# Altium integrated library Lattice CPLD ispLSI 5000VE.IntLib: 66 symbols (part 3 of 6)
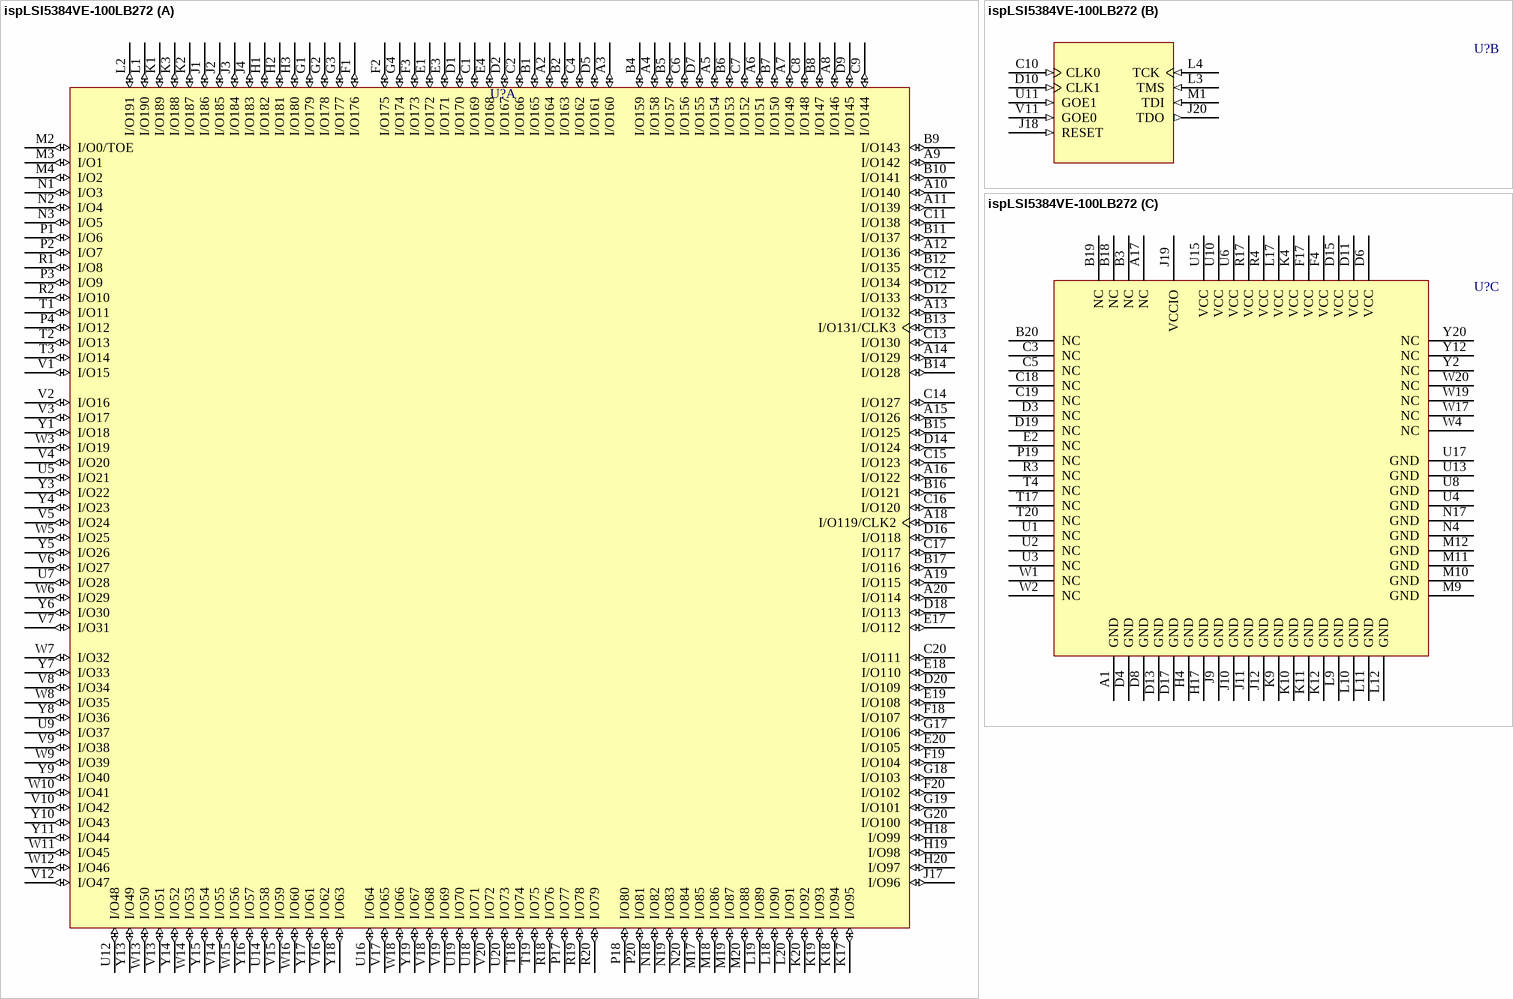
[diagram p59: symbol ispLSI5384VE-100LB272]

## ispLSI5384VE-100LB272
designator U?
ispLSI 5384VE SuperWIDE High Density PLD with 144 User I/Os, 10 ns, 3.3 V, Commercial Grade
footprint BGA272 (BGA, 272-Leads, Body 27x27mm, Pitch 1.27mm)
3D model 5384VE-BGA272 (272-Ball Ball Grid Array (BGA272))
part A pins: A2 I/O164 (io), A3 I/O160 (io), A4 I/O158 (io), A5 I/O154 (io), A6 I/O151 (io), A7 I/O149 (io), A8 I/O146 (io), A9 I/O142 (io), A10 I/O140 (io), A11 I/O139 (io), A12 I/O136 (io), A13 I/O132 (io), A14 I/O129 (io), A15 I/O126 (io), A16 I/O122 (io), A18 I/O119/CLK2 (io), A19 I/O115 (io), A20 I/O114 (io), B1 I/O165 (io), B2 I/O163 (io), B4 I/O159 (io), B5 I/O157 (io), B6 I/O153 (io), B7 I/O150 (io), B8 I/O147 (io), B9 I/O143 (io), B10 I/O141 (io), B11 I/O137 (io), B12 I/O135 (io), B13 I/O131/CLK3 (io), B14 I/O128 (io), B15 I/O125 (io), B16 I/O121 (io), B17 I/O116 (io), C1 I/O169 (io), C2 I/O166 (io), C4 I/O162 (io), C6 I/O156 (io), C7 I/O152 (io), C8 I/O148 (io), C9 I/O144 (io), C11 I/O138 (io), C12 I/O134 (io), C13 I/O130 (io), C14 I/O127 (io), C15 I/O123 (io), C16 I/O120 (io), C17 I/O117 (io), C20 I/O111 (io), D1 I/O170 (io), D2 I/O167 (io), D5 I/O161 (io), D7 I/O155 (io), D9 I/O145 (io), D12 I/O133 (io), D14 I/O124 (io), D16 I/O118 (io), D18 I/O113 (io), D20 I/O109 (io), E1 I/O172 (io), E3 I/O171 (io), E4 I/O168 (io), E17 I/O112 (io), E18 I/O110 (io), E19 I/O108 (io), E20 I/O105 (io), F1 I/O176 (io), F2 I/O175 (io), F3 I/O173 (io), F18 I/O107 (io), F19 I/O104 (io), F20 I/O102 (io), G1 I/O179 (io), G2 I/O178 (io), G3 I/O177 (io), G4 I/O174 (io), G17 I/O106 (io), G18 I/O103 (io), G19 I/O101 (io), G20 I/O100 (io), H1 I/O182 (io), H2 I/O181 (io), H3 I/O180 (io), H18 I/O99 (io), H19 I/O98 (io), H20 I/O97 (io), J1 I/O186 (io), J2 I/O185 (io), J3 I/O184 (io), J4 I/O183 (io), J17 I/O96 (io), K1 I/O189 (io), K2 I/O187 (io), K3 I/O188 (io), K17 I/O95 (io), K18 I/O94 (io), K19 I/O93 (io), K20 I/O92 (io), L1 I/O190 (io), L2 I/O191 (io), L18 I/O90 (io), L19 I/O89 (io), L20 I/O91 (io), M2 I/O0/TOE (io), M3 I/O1 (io), M4 I/O2 (io), M17 I/O85 (io), M18 I/O86 (io), M19 I/O87 (io), M20 I/O88 (io), N1 I/O3 (io), N2 I/O4 (io), N3 I/O5 (io), N18 I/O82 (io), N19 I/O83 (io), N20 I/O84 (io), P1 I/O6 (io), P2 I/O7 (io), P3 I/O9 (io), P4 I/O12 (io), P17 I/O77 (io), P18 I/O80 (io), P20 I/O81 (io), R1 I/O8 (io), R2 I/O10 (io), R18 I/O76 (io), R19 I/O78 (io), R20 I/O79 (io), T1 I/O11 (io), T2 I/O13 (io), T3 I/O14 (io), T18 I/O74 (io), T19 I/O75 (io), U5 I/O21 (io), U7 I/O28 (io), U9 I/O37 (io), U12 I/O48 (io), U14 I/O58 (io), U16 I/O64 (io), U18 I/O71 (io), U19 I/O70 (io), U20 I/O73 (io), V1 I/O15 (io), V2 I/O16 (io), V3 I/O17 (io), V4 I/O20 (io), V5 I/O24 (io), V6 I/O27 (io), V7 I/O31 (io), V8 I/O34 (io), V9 I/O38 (io), V10 I/O42 (io), V12 I/O47 (io), V13 I/O51 (io), V14 I/O55 (io), V15 I/O59 (io), V16 I/O62 (io), V17 I/O65 (io), V18 I/O68 (io), V19 I/O69 (io), V20 I/O72 (io), W3 I/O19 (io), W5 I/O25 (io), W6 I/O29 (io), W7 I/O32 (io), W8 I/O35 (io), W9 I/O39 (io), W10 I/O41 (io), W11 I/O45 (io), W12 I/O46 (io), W13 I/O50 (io), W14 I/O53 (io), W15 I/O56 (io), W16 I/O60 (io), W18 I/O66 (io), Y1 I/O18 (io), Y3 I/O22 (io), Y4 I/O23 (io), Y5 I/O26 (io), Y6 I/O30 (io), Y7 I/O33 (io), Y8 I/O36 (io), Y9 I/O40 (io), Y10 I/O43 (io), Y11 I/O44 (io), Y13 I/O49 (io), Y14 I/O52 (io), Y15 I/O54 (io), Y16 I/O57 (io), Y17 I/O61 (io), Y18 I/O63 (io), Y19 I/O67 (io)
part B pins: C10 CLK0 (in), D10 CLK1 (in), J18 RESET (in), J20 TDO (out), L3 TMS (in), L4 TCK (in), M1 TDI (in), U11 GOE1 (in), V11 GOE0 (in)
part C pins: A1 GND (power), A17 NC, B3 NC, B18 NC, B19 NC, B20 NC, C3 NC, C5 NC, C18 NC, C19 NC, D3 NC, D4 GND (power), D6 VCC (power), D8 GND (power), D11 VCC (power), D13 GND (power), D15 VCC (power), D17 GND (power), D19 NC, E2 NC, F4 VCC (power), F17 VCC (power), H4 GND (power), H17 GND (power), J9 GND (power), J10 GND (power), J11 GND (power), J12 GND (power), J19 VCCIO (power), K4 VCC (power), K9 GND (power), K10 GND (power), K11 GND (power), K12 GND (power), L9 GND (power), L10 GND (power), L11 GND (power), L12 GND (power), L17 VCC (power), M9 GND (power), M10 GND (power), M11 GND (power), M12 GND (power), N4 GND (power), N17 GND (power), P19 NC, R3 NC, R4 VCC (power), R17 VCC (power), T4 NC, T17 NC, T20 NC, U1 NC, U2 NC, U3 NC, U4 GND (power), U6 VCC (power), U8 GND (power), U10 VCC (power), U13 GND (power), U15 VCC (power), U17 GND (power), W1 NC, W2 NC, W4 NC, W17 NC, W19 NC, W20 NC, Y2 NC, Y12 NC, Y20 NC

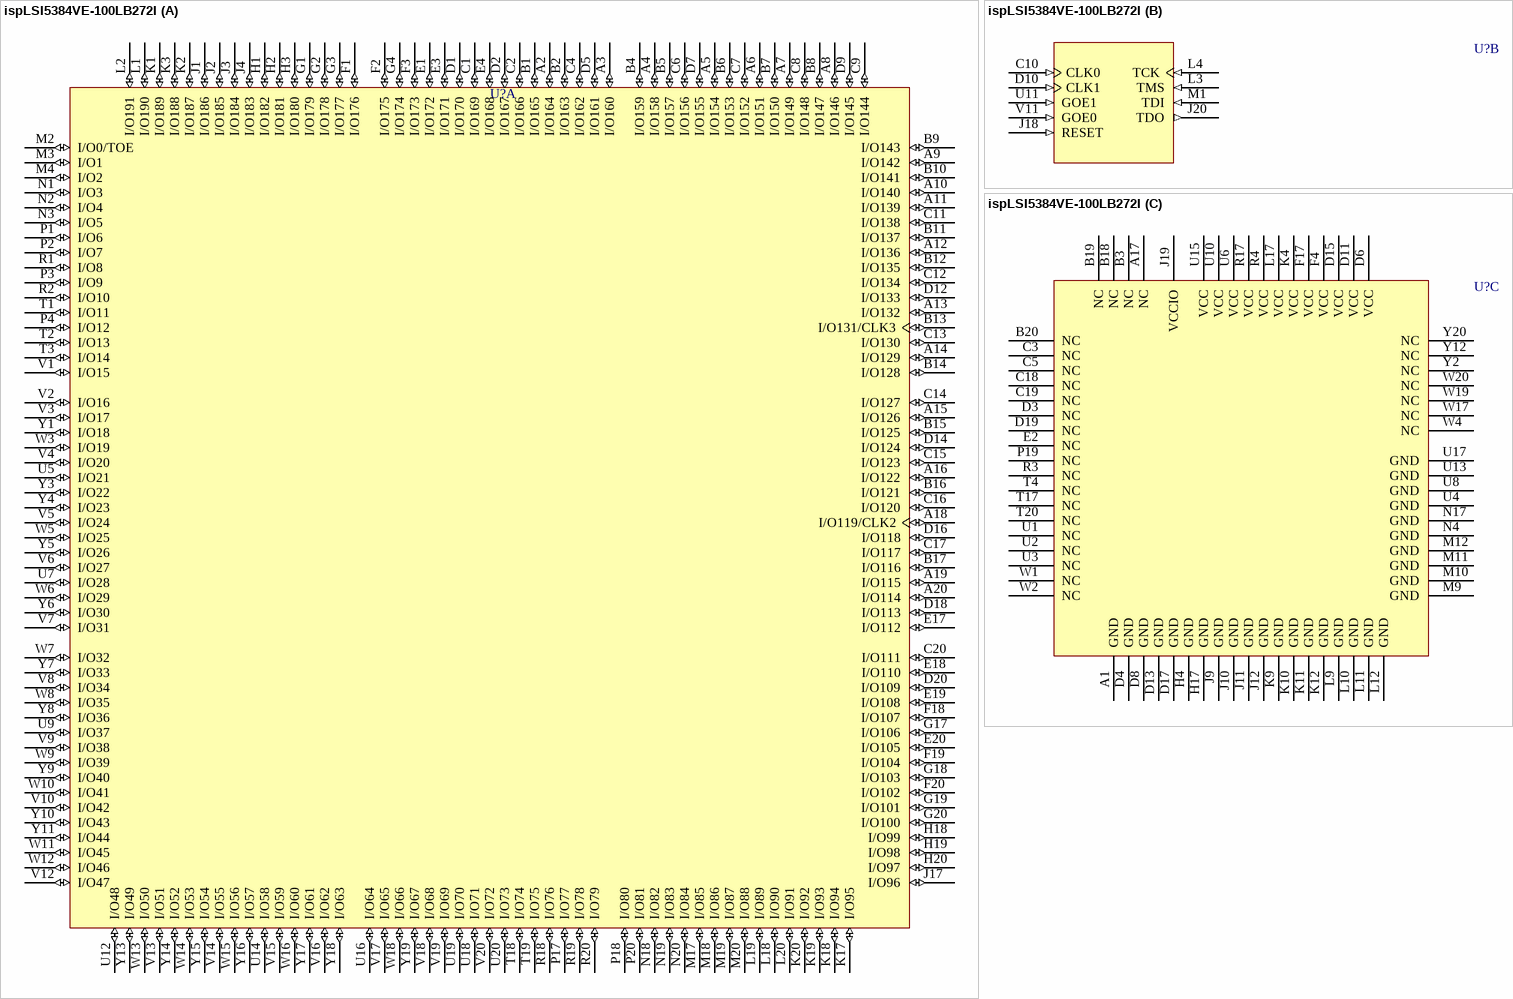
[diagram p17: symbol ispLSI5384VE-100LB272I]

## ispLSI5384VE-100LB272I
designator U?
ispLSI 5384VE SuperWIDE High Density PLD with 144 User I/Os, 10 ns, 3.3 V, Industrial Grade
footprint BGA272 (BGA, 272-Leads, Body 27x27mm, Pitch 1.27mm)
3D model 5384VE-BGA272 (272-Ball Ball Grid Array (BGA272))
part A pins: A2 I/O164 (io), A3 I/O160 (io), A4 I/O158 (io), A5 I/O154 (io), A6 I/O151 (io), A7 I/O149 (io), A8 I/O146 (io), A9 I/O142 (io), A10 I/O140 (io), A11 I/O139 (io), A12 I/O136 (io), A13 I/O132 (io), A14 I/O129 (io), A15 I/O126 (io), A16 I/O122 (io), A18 I/O119/CLK2 (io), A19 I/O115 (io), A20 I/O114 (io), B1 I/O165 (io), B2 I/O163 (io), B4 I/O159 (io), B5 I/O157 (io), B6 I/O153 (io), B7 I/O150 (io), B8 I/O147 (io), B9 I/O143 (io), B10 I/O141 (io), B11 I/O137 (io), B12 I/O135 (io), B13 I/O131/CLK3 (io), B14 I/O128 (io), B15 I/O125 (io), B16 I/O121 (io), B17 I/O116 (io), C1 I/O169 (io), C2 I/O166 (io), C4 I/O162 (io), C6 I/O156 (io), C7 I/O152 (io), C8 I/O148 (io), C9 I/O144 (io), C11 I/O138 (io), C12 I/O134 (io), C13 I/O130 (io), C14 I/O127 (io), C15 I/O123 (io), C16 I/O120 (io), C17 I/O117 (io), C20 I/O111 (io), D1 I/O170 (io), D2 I/O167 (io), D5 I/O161 (io), D7 I/O155 (io), D9 I/O145 (io), D12 I/O133 (io), D14 I/O124 (io), D16 I/O118 (io), D18 I/O113 (io), D20 I/O109 (io), E1 I/O172 (io), E3 I/O171 (io), E4 I/O168 (io), E17 I/O112 (io), E18 I/O110 (io), E19 I/O108 (io), E20 I/O105 (io), F1 I/O176 (io), F2 I/O175 (io), F3 I/O173 (io), F18 I/O107 (io), F19 I/O104 (io), F20 I/O102 (io), G1 I/O179 (io), G2 I/O178 (io), G3 I/O177 (io), G4 I/O174 (io), G17 I/O106 (io), G18 I/O103 (io), G19 I/O101 (io), G20 I/O100 (io), H1 I/O182 (io), H2 I/O181 (io), H3 I/O180 (io), H18 I/O99 (io), H19 I/O98 (io), H20 I/O97 (io), J1 I/O186 (io), J2 I/O185 (io), J3 I/O184 (io), J4 I/O183 (io), J17 I/O96 (io), K1 I/O189 (io), K2 I/O187 (io), K3 I/O188 (io), K17 I/O95 (io), K18 I/O94 (io), K19 I/O93 (io), K20 I/O92 (io), L1 I/O190 (io), L2 I/O191 (io), L18 I/O90 (io), L19 I/O89 (io), L20 I/O91 (io), M2 I/O0/TOE (io), M3 I/O1 (io), M4 I/O2 (io), M17 I/O85 (io), M18 I/O86 (io), M19 I/O87 (io), M20 I/O88 (io), N1 I/O3 (io), N2 I/O4 (io), N3 I/O5 (io), N18 I/O82 (io), N19 I/O83 (io), N20 I/O84 (io), P1 I/O6 (io), P2 I/O7 (io), P3 I/O9 (io), P4 I/O12 (io), P17 I/O77 (io), P18 I/O80 (io), P20 I/O81 (io), R1 I/O8 (io), R2 I/O10 (io), R18 I/O76 (io), R19 I/O78 (io), R20 I/O79 (io), T1 I/O11 (io), T2 I/O13 (io), T3 I/O14 (io), T18 I/O74 (io), T19 I/O75 (io), U5 I/O21 (io), U7 I/O28 (io), U9 I/O37 (io), U12 I/O48 (io), U14 I/O58 (io), U16 I/O64 (io), U18 I/O71 (io), U19 I/O70 (io), U20 I/O73 (io), V1 I/O15 (io), V2 I/O16 (io), V3 I/O17 (io), V4 I/O20 (io), V5 I/O24 (io), V6 I/O27 (io), V7 I/O31 (io), V8 I/O34 (io), V9 I/O38 (io), V10 I/O42 (io), V12 I/O47 (io), V13 I/O51 (io), V14 I/O55 (io), V15 I/O59 (io), V16 I/O62 (io), V17 I/O65 (io), V18 I/O68 (io), V19 I/O69 (io), V20 I/O72 (io), W3 I/O19 (io), W5 I/O25 (io), W6 I/O29 (io), W7 I/O32 (io), W8 I/O35 (io), W9 I/O39 (io), W10 I/O41 (io), W11 I/O45 (io), W12 I/O46 (io), W13 I/O50 (io), W14 I/O53 (io), W15 I/O56 (io), W16 I/O60 (io), W18 I/O66 (io), Y1 I/O18 (io), Y3 I/O22 (io), Y4 I/O23 (io), Y5 I/O26 (io), Y6 I/O30 (io), Y7 I/O33 (io), Y8 I/O36 (io), Y9 I/O40 (io), Y10 I/O43 (io), Y11 I/O44 (io), Y13 I/O49 (io), Y14 I/O52 (io), Y15 I/O54 (io), Y16 I/O57 (io), Y17 I/O61 (io), Y18 I/O63 (io), Y19 I/O67 (io)
part B pins: C10 CLK0 (in), D10 CLK1 (in), J18 RESET (in), J20 TDO (out), L3 TMS (in), L4 TCK (in), M1 TDI (in), U11 GOE1 (in), V11 GOE0 (in)
part C pins: A1 GND (power), A17 NC, B3 NC, B18 NC, B19 NC, B20 NC, C3 NC, C5 NC, C18 NC, C19 NC, D3 NC, D4 GND (power), D6 VCC (power), D8 GND (power), D11 VCC (power), D13 GND (power), D15 VCC (power), D17 GND (power), D19 NC, E2 NC, F4 VCC (power), F17 VCC (power), H4 GND (power), H17 GND (power), J9 GND (power), J10 GND (power), J11 GND (power), J12 GND (power), J19 VCCIO (power), K4 VCC (power), K9 GND (power), K10 GND (power), K11 GND (power), K12 GND (power), L9 GND (power), L10 GND (power), L11 GND (power), L12 GND (power), L17 VCC (power), M9 GND (power), M10 GND (power), M11 GND (power), M12 GND (power), N4 GND (power), N17 GND (power), P19 NC, R3 NC, R4 VCC (power), R17 VCC (power), T4 NC, T17 NC, T20 NC, U1 NC, U2 NC, U3 NC, U4 GND (power), U6 VCC (power), U8 GND (power), U10 VCC (power), U13 GND (power), U15 VCC (power), U17 GND (power), W1 NC, W2 NC, W4 NC, W17 NC, W19 NC, W20 NC, Y2 NC, Y12 NC, Y20 NC

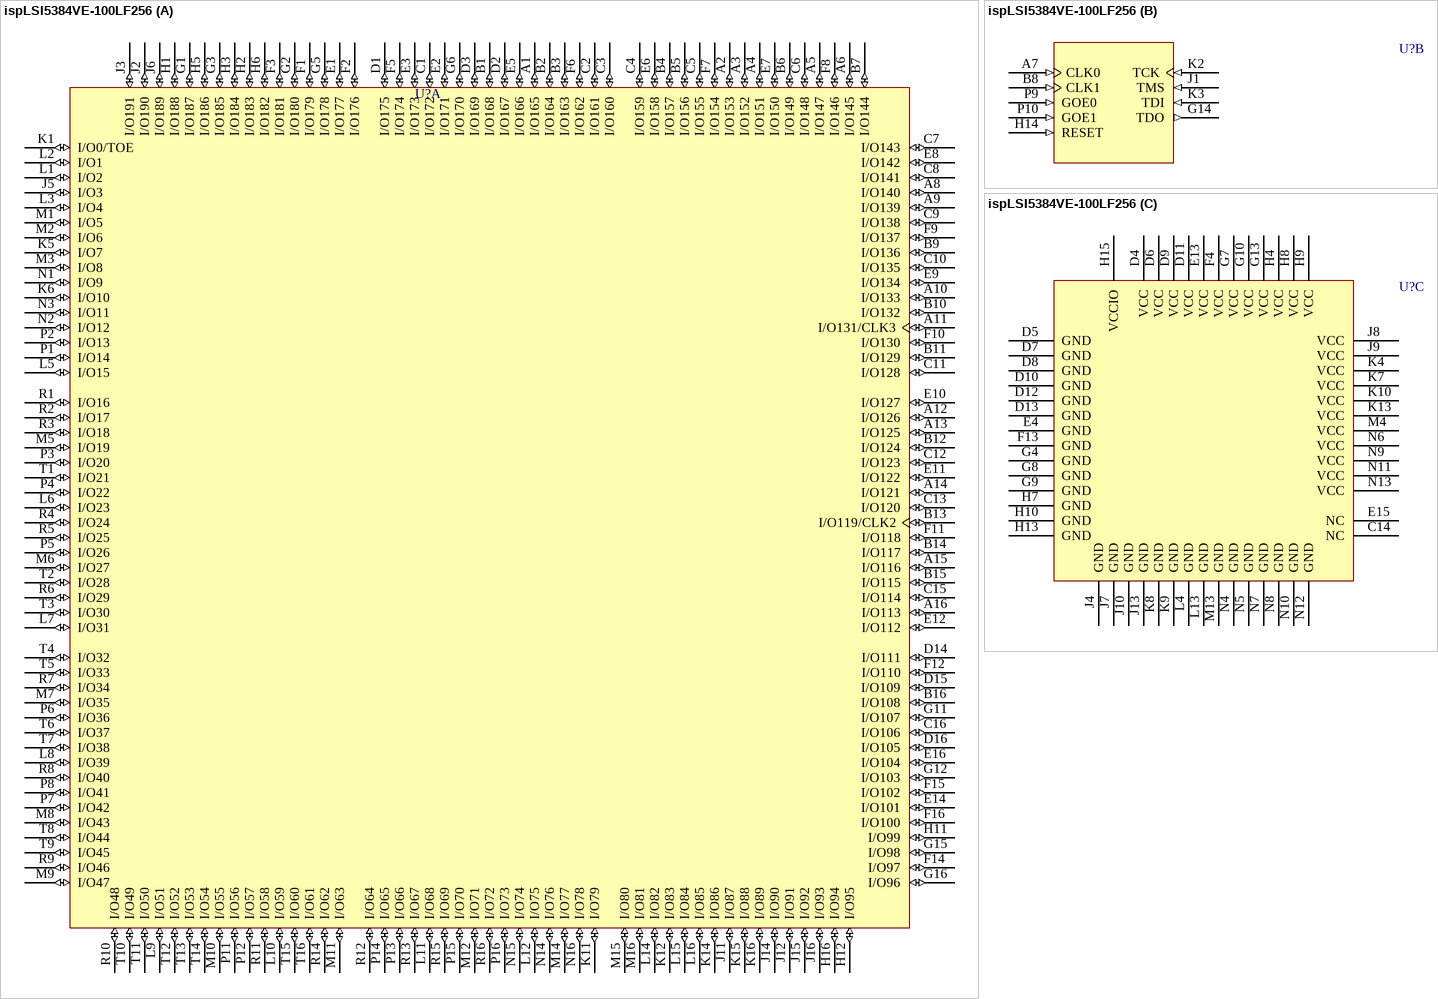
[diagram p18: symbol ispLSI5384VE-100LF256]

## ispLSI5384VE-100LF256
designator U?
ispLSI 5384VE SuperWIDE High Density PLD with 192 User I/Os, 10 ns, 3.3 V, Commercial Grade
footprint fpBGA256 (BGA, 256-Leads, Body 17x17mm, Pitch 1mm)
3D model 5384VE-fpBGA256 (256-Ball Fine Pitch Ball Grid Array (fpBGA256))
part A pins: A1 I/O165 (io), A2 I/O153 (io), A3 I/O152 (io), A4 I/O151 (io), A5 I/O147 (io), A6 I/O145 (io), A8 I/O140 (io), A9 I/O139 (io), A10 I/O133 (io), A11 I/O131/CLK3 (io), A12 I/O126 (io), A13 I/O125 (io), A14 I/O121 (io), A15 I/O116 (io), A16 I/O113 (io), B1 I/O168 (io), B2 I/O164 (io), B3 I/O163 (io), B4 I/O157 (io), B5 I/O156 (io), B6 I/O149 (io), B7 I/O144 (io), B9 I/O136 (io), B10 I/O132 (io), B11 I/O129 (io), B12 I/O124 (io), B13 I/O119/CLK2 (io), B14 I/O117 (io), B15 I/O115 (io), B16 I/O108 (io), C1 I/O172 (io), C2 I/O161 (io), C3 I/O160 (io), C4 I/O159 (io), C5 I/O155 (io), C6 I/O148 (io), C7 I/O143 (io), C8 I/O141 (io), C9 I/O138 (io), C10 I/O135 (io), C11 I/O128 (io), C12 I/O123 (io), C13 I/O120 (io), C15 I/O114 (io), C16 I/O106 (io), D1 I/O175 (io), D2 I/O167 (io), D3 I/O169 (io), D14 I/O111 (io), D15 I/O109 (io), D16 I/O105 (io), E1 I/O177 (io), E2 I/O171 (io), E3 I/O173 (io), E5 I/O166 (io), E6 I/O158 (io), E7 I/O150 (io), E8 I/O142 (io), E9 I/O134 (io), E10 I/O127 (io), E11 I/O122 (io), E12 I/O112 (io), E14 I/O101 (io), E16 I/O104 (io), F1 I/O179 (io), F2 I/O176 (io), F3 I/O181 (io), F5 I/O174 (io), F6 I/O162 (io), F7 I/O154 (io), F8 I/O146 (io), F9 I/O137 (io), F10 I/O130 (io), F11 I/O118 (io), F12 I/O110 (io), F14 I/O97 (io), F15 I/O102 (io), F16 I/O100 (io), G1 I/O187 (io), G2 I/O180 (io), G3 I/O185 (io), G5 I/O178 (io), G6 I/O170 (io), G11 I/O107 (io), G12 I/O103 (io), G15 I/O98 (io), G16 I/O96 (io), H1 I/O188 (io), H2 I/O183 (io), H3 I/O184 (io), H5 I/O186 (io), H6 I/O182 (io), H11 I/O99 (io), H12 I/O95 (io), H16 I/O94 (io), J2 I/O190 (io), J3 I/O191 (io), J5 I/O3 (io), J6 I/O189 (io), J11 I/O87 (io), J12 I/O91 (io), J14 I/O90 (io), J15 I/O92 (io), J16 I/O93 (io), K1 I/O0/TOE (io), K5 I/O7 (io), K6 I/O10 (io), K11 I/O79 (io), K12 I/O83 (io), K14 I/O86 (io), K15 I/O88 (io), K16 I/O89 (io), L1 I/O2 (io), L2 I/O1 (io), L3 I/O4 (io), L5 I/O15 (io), L6 I/O23 (io), L7 I/O31 (io), L8 I/O39 (io), L9 I/O51 (io), L10 I/O59 (io), L11 I/O68 (io), L12 I/O75 (io), L14 I/O82 (io), L15 I/O84 (io), L16 I/O85 (io), M1 I/O5 (io), M2 I/O6 (io), M3 I/O8 (io), M5 I/O19 (io), M6 I/O27 (io), M7 I/O35 (io), M8 I/O43 (io), M9 I/O47 (io), M10 I/O55 (io), M11 I/O63 (io), M12 I/O71 (io), M14 I/O77 (io), M15 I/O80 (io), M16 I/O81 (io), N1 I/O9 (io), N2 I/O12 (io), N3 I/O11 (io), N14 I/O76 (io), N15 I/O74 (io), N16 I/O78 (io), P1 I/O14 (io), P2 I/O13 (io), P3 I/O20 (io), P4 I/O22 (io), P5 I/O26 (io), P6 I/O36 (io), P7 I/O42 (io), P8 I/O41 (io), P11 I/O56 (io), P12 I/O57 (io), P13 I/O66 (io), P14 I/O65 (io), P15 I/O70 (io), P16 I/O73 (io), R1 I/O16 (io), R2 I/O17 (io), R3 I/O18 (io), R4 I/O24 (io), R5 I/O25 (io), R6 I/O29 (io), R7 I/O34 (io), R8 I/O40 (io), R9 I/O46 (io), R10 I/O48 (io), R11 I/O58 (io), R12 I/O64 (io), R13 I/O67 (io), R14 I/O62 (io), R15 I/O69 (io), R16 I/O72 (io), T1 I/O21 (io), T2 I/O28 (io), T3 I/O30 (io), T4 I/O32 (io), T5 I/O33 (io), T6 I/O37 (io), T7 I/O38 (io), T8 I/O44 (io), T9 I/O45 (io), T10 I/O49 (io), T11 I/O50 (io), T12 I/O52 (io), T13 I/O53 (io), T14 I/O54 (io), T15 I/O60 (io), T16 I/O61 (io)
part B pins: A7 CLK0 (in), B8 CLK1 (in), G14 TDO (out), H14 RESET (in), J1 TMS (in), K2 TCK (in), K3 TDI (in), P9 GOE0 (in), P10 GOE1 (in)
part C pins: C14 NC, D4 VCC (power), D5 GND (power), D6 VCC (power), D7 GND (power), D8 GND (power), D9 VCC (power), D10 GND (power), D11 VCC (power), D12 GND (power), D13 GND (power), E4 GND (power), E13 VCC (power), E15 NC, F4 VCC (power), F13 GND (power), G4 GND (power), G7 VCC (power), G8 GND (power), G9 GND (power), G10 VCC (power), G13 VCC (power), H4 VCC (power), H7 GND (power), H8 VCC (power), H9 VCC (power), H10 GND (power), H13 GND (power), H15 VCCIO (power), J4 GND (power), J7 GND (power), J8 VCC (power), J9 VCC (power), J10 GND (power), J13 GND (power), K4 VCC (power), K7 VCC (power), K8 GND (power), K9 GND (power), K10 VCC (power), K13 VCC (power), L4 GND (power), L13 GND (power), M4 VCC (power), M13 GND (power), N4 GND (power), N5 GND (power), N6 VCC (power), N7 GND (power), N8 GND (power), N9 VCC (power), N10 GND (power), N11 VCC (power), N12 GND (power), N13 VCC (power)

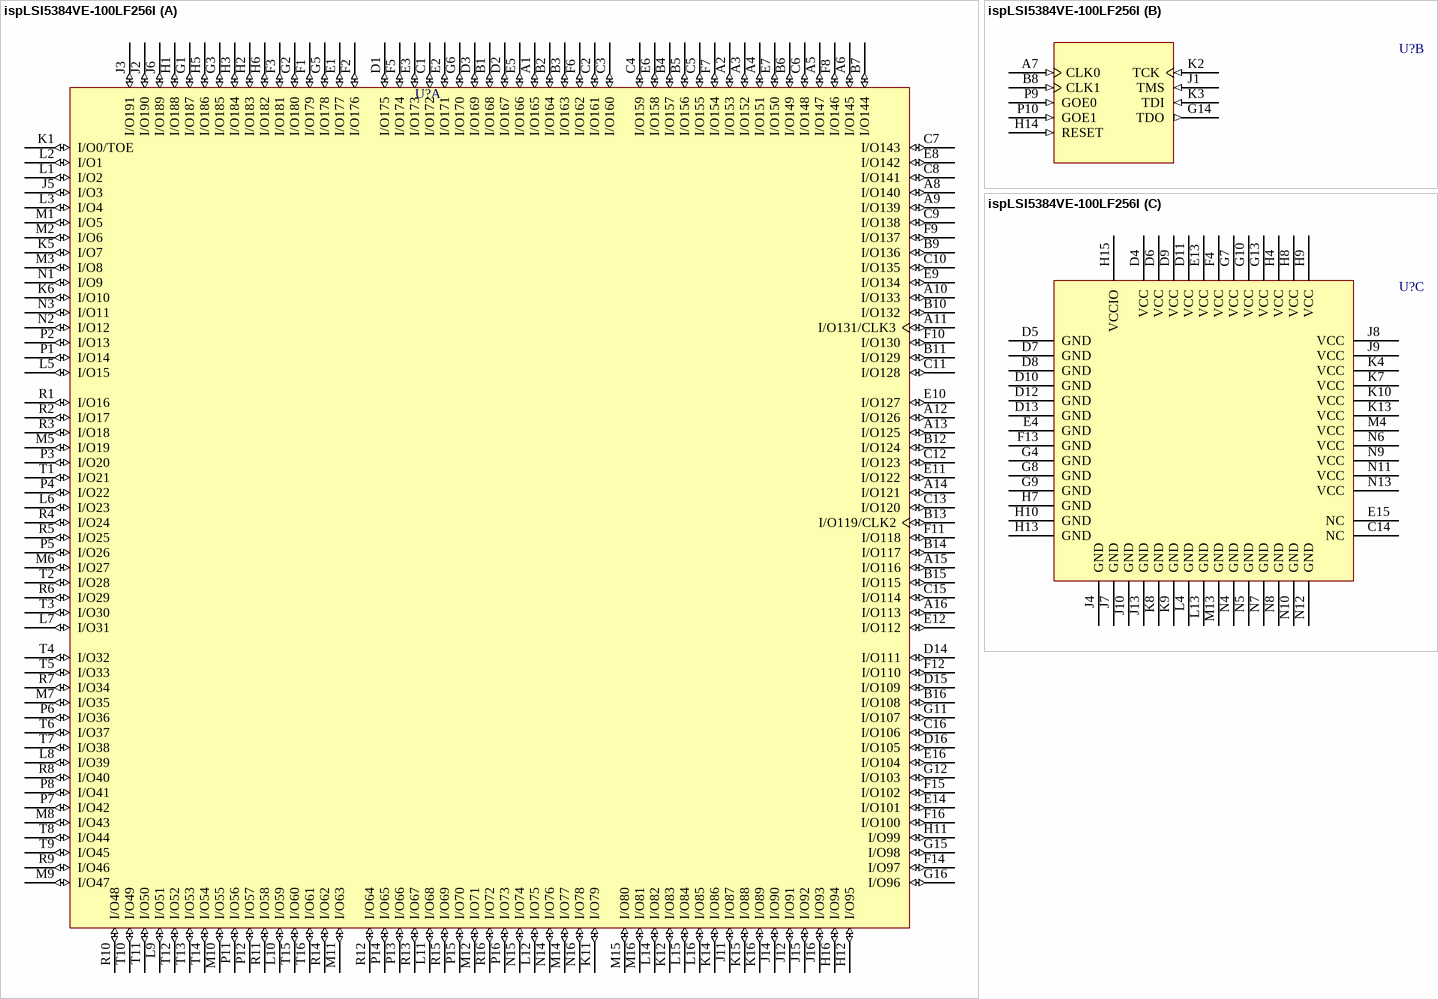
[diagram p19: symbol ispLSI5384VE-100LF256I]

## ispLSI5384VE-100LF256I
designator U?
ispLSI 5384VE SuperWIDE High Density PLD with 192 User I/Os, 10 ns, 3.3 V, Industrial Grade
footprint fpBGA256 (BGA, 256-Leads, Body 17x17mm, Pitch 1mm)
3D model 5384VE-fpBGA256 (256-Ball Fine Pitch Ball Grid Array (fpBGA256))
part A pins: A1 I/O165 (io), A2 I/O153 (io), A3 I/O152 (io), A4 I/O151 (io), A5 I/O147 (io), A6 I/O145 (io), A8 I/O140 (io), A9 I/O139 (io), A10 I/O133 (io), A11 I/O131/CLK3 (io), A12 I/O126 (io), A13 I/O125 (io), A14 I/O121 (io), A15 I/O116 (io), A16 I/O113 (io), B1 I/O168 (io), B2 I/O164 (io), B3 I/O163 (io), B4 I/O157 (io), B5 I/O156 (io), B6 I/O149 (io), B7 I/O144 (io), B9 I/O136 (io), B10 I/O132 (io), B11 I/O129 (io), B12 I/O124 (io), B13 I/O119/CLK2 (io), B14 I/O117 (io), B15 I/O115 (io), B16 I/O108 (io), C1 I/O172 (io), C2 I/O161 (io), C3 I/O160 (io), C4 I/O159 (io), C5 I/O155 (io), C6 I/O148 (io), C7 I/O143 (io), C8 I/O141 (io), C9 I/O138 (io), C10 I/O135 (io), C11 I/O128 (io), C12 I/O123 (io), C13 I/O120 (io), C15 I/O114 (io), C16 I/O106 (io), D1 I/O175 (io), D2 I/O167 (io), D3 I/O169 (io), D14 I/O111 (io), D15 I/O109 (io), D16 I/O105 (io), E1 I/O177 (io), E2 I/O171 (io), E3 I/O173 (io), E5 I/O166 (io), E6 I/O158 (io), E7 I/O150 (io), E8 I/O142 (io), E9 I/O134 (io), E10 I/O127 (io), E11 I/O122 (io), E12 I/O112 (io), E14 I/O101 (io), E16 I/O104 (io), F1 I/O179 (io), F2 I/O176 (io), F3 I/O181 (io), F5 I/O174 (io), F6 I/O162 (io), F7 I/O154 (io), F8 I/O146 (io), F9 I/O137 (io), F10 I/O130 (io), F11 I/O118 (io), F12 I/O110 (io), F14 I/O97 (io), F15 I/O102 (io), F16 I/O100 (io), G1 I/O187 (io), G2 I/O180 (io), G3 I/O185 (io), G5 I/O178 (io), G6 I/O170 (io), G11 I/O107 (io), G12 I/O103 (io), G15 I/O98 (io), G16 I/O96 (io), H1 I/O188 (io), H2 I/O183 (io), H3 I/O184 (io), H5 I/O186 (io), H6 I/O182 (io), H11 I/O99 (io), H12 I/O95 (io), H16 I/O94 (io), J2 I/O190 (io), J3 I/O191 (io), J5 I/O3 (io), J6 I/O189 (io), J11 I/O87 (io), J12 I/O91 (io), J14 I/O90 (io), J15 I/O92 (io), J16 I/O93 (io), K1 I/O0/TOE (io), K5 I/O7 (io), K6 I/O10 (io), K11 I/O79 (io), K12 I/O83 (io), K14 I/O86 (io), K15 I/O88 (io), K16 I/O89 (io), L1 I/O2 (io), L2 I/O1 (io), L3 I/O4 (io), L5 I/O15 (io), L6 I/O23 (io), L7 I/O31 (io), L8 I/O39 (io), L9 I/O51 (io), L10 I/O59 (io), L11 I/O68 (io), L12 I/O75 (io), L14 I/O82 (io), L15 I/O84 (io), L16 I/O85 (io), M1 I/O5 (io), M2 I/O6 (io), M3 I/O8 (io), M5 I/O19 (io), M6 I/O27 (io), M7 I/O35 (io), M8 I/O43 (io), M9 I/O47 (io), M10 I/O55 (io), M11 I/O63 (io), M12 I/O71 (io), M14 I/O77 (io), M15 I/O80 (io), M16 I/O81 (io), N1 I/O9 (io), N2 I/O12 (io), N3 I/O11 (io), N14 I/O76 (io), N15 I/O74 (io), N16 I/O78 (io), P1 I/O14 (io), P2 I/O13 (io), P3 I/O20 (io), P4 I/O22 (io), P5 I/O26 (io), P6 I/O36 (io), P7 I/O42 (io), P8 I/O41 (io), P11 I/O56 (io), P12 I/O57 (io), P13 I/O66 (io), P14 I/O65 (io), P15 I/O70 (io), P16 I/O73 (io), R1 I/O16 (io), R2 I/O17 (io), R3 I/O18 (io), R4 I/O24 (io), R5 I/O25 (io), R6 I/O29 (io), R7 I/O34 (io), R8 I/O40 (io), R9 I/O46 (io), R10 I/O48 (io), R11 I/O58 (io), R12 I/O64 (io), R13 I/O67 (io), R14 I/O62 (io), R15 I/O69 (io), R16 I/O72 (io), T1 I/O21 (io), T2 I/O28 (io), T3 I/O30 (io), T4 I/O32 (io), T5 I/O33 (io), T6 I/O37 (io), T7 I/O38 (io), T8 I/O44 (io), T9 I/O45 (io), T10 I/O49 (io), T11 I/O50 (io), T12 I/O52 (io), T13 I/O53 (io), T14 I/O54 (io), T15 I/O60 (io), T16 I/O61 (io)
part B pins: A7 CLK0 (in), B8 CLK1 (in), G14 TDO (out), H14 RESET (in), J1 TMS (in), K2 TCK (in), K3 TDI (in), P9 GOE0 (in), P10 GOE1 (in)
part C pins: C14 NC, D4 VCC (power), D5 GND (power), D6 VCC (power), D7 GND (power), D8 GND (power), D9 VCC (power), D10 GND (power), D11 VCC (power), D12 GND (power), D13 GND (power), E4 GND (power), E13 VCC (power), E15 NC, F4 VCC (power), F13 GND (power), G4 GND (power), G7 VCC (power), G8 GND (power), G9 GND (power), G10 VCC (power), G13 VCC (power), H4 VCC (power), H7 GND (power), H8 VCC (power), H9 VCC (power), H10 GND (power), H13 GND (power), H15 VCCIO (power), J4 GND (power), J7 GND (power), J8 VCC (power), J9 VCC (power), J10 GND (power), J13 GND (power), K4 VCC (power), K7 VCC (power), K8 GND (power), K9 GND (power), K10 VCC (power), K13 VCC (power), L4 GND (power), L13 GND (power), M4 VCC (power), M13 GND (power), N4 GND (power), N5 GND (power), N6 VCC (power), N7 GND (power), N8 GND (power), N9 VCC (power), N10 GND (power), N11 VCC (power), N12 GND (power), N13 VCC (power)

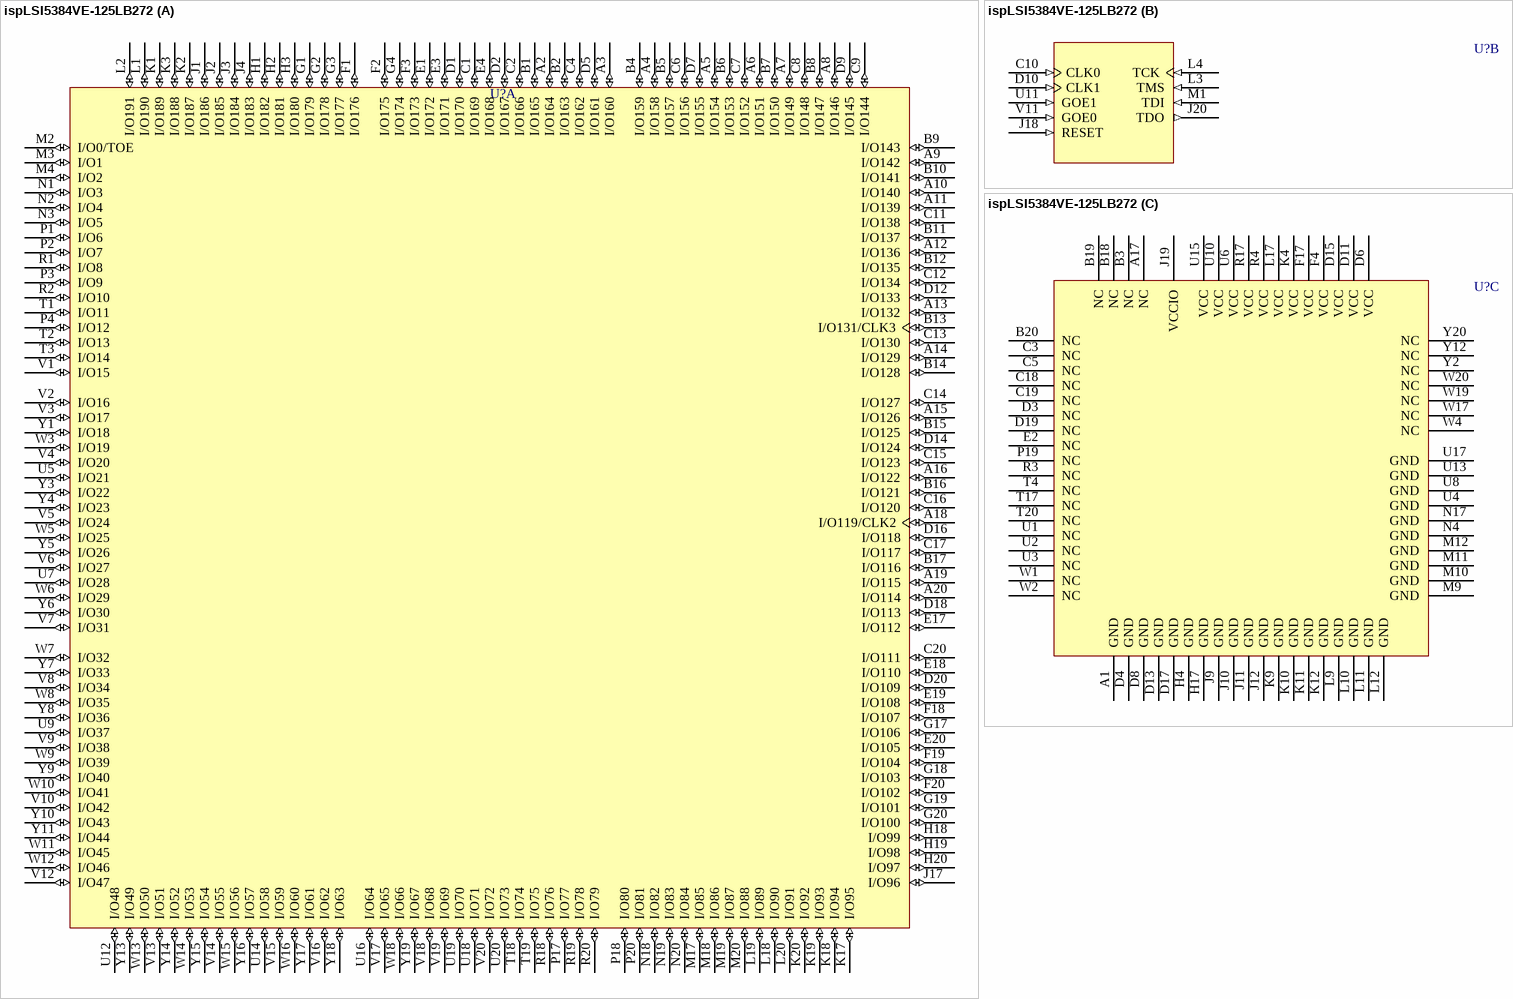
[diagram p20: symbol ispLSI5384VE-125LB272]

## ispLSI5384VE-125LB272
designator U?
ispLSI 5384VE SuperWIDE High Density PLD with 144 User I/Os, 7.5 ns, 3.3 V, Commercial Grade
footprint BGA272 (BGA, 272-Leads, Body 27x27mm, Pitch 1.27mm)
3D model 5384VE-BGA272 (272-Ball Ball Grid Array (BGA272))
part A pins: A2 I/O164 (io), A3 I/O160 (io), A4 I/O158 (io), A5 I/O154 (io), A6 I/O151 (io), A7 I/O149 (io), A8 I/O146 (io), A9 I/O142 (io), A10 I/O140 (io), A11 I/O139 (io), A12 I/O136 (io), A13 I/O132 (io), A14 I/O129 (io), A15 I/O126 (io), A16 I/O122 (io), A18 I/O119/CLK2 (io), A19 I/O115 (io), A20 I/O114 (io), B1 I/O165 (io), B2 I/O163 (io), B4 I/O159 (io), B5 I/O157 (io), B6 I/O153 (io), B7 I/O150 (io), B8 I/O147 (io), B9 I/O143 (io), B10 I/O141 (io), B11 I/O137 (io), B12 I/O135 (io), B13 I/O131/CLK3 (io), B14 I/O128 (io), B15 I/O125 (io), B16 I/O121 (io), B17 I/O116 (io), C1 I/O169 (io), C2 I/O166 (io), C4 I/O162 (io), C6 I/O156 (io), C7 I/O152 (io), C8 I/O148 (io), C9 I/O144 (io), C11 I/O138 (io), C12 I/O134 (io), C13 I/O130 (io), C14 I/O127 (io), C15 I/O123 (io), C16 I/O120 (io), C17 I/O117 (io), C20 I/O111 (io), D1 I/O170 (io), D2 I/O167 (io), D5 I/O161 (io), D7 I/O155 (io), D9 I/O145 (io), D12 I/O133 (io), D14 I/O124 (io), D16 I/O118 (io), D18 I/O113 (io), D20 I/O109 (io), E1 I/O172 (io), E3 I/O171 (io), E4 I/O168 (io), E17 I/O112 (io), E18 I/O110 (io), E19 I/O108 (io), E20 I/O105 (io), F1 I/O176 (io), F2 I/O175 (io), F3 I/O173 (io), F18 I/O107 (io), F19 I/O104 (io), F20 I/O102 (io), G1 I/O179 (io), G2 I/O178 (io), G3 I/O177 (io), G4 I/O174 (io), G17 I/O106 (io), G18 I/O103 (io), G19 I/O101 (io), G20 I/O100 (io), H1 I/O182 (io), H2 I/O181 (io), H3 I/O180 (io), H18 I/O99 (io), H19 I/O98 (io), H20 I/O97 (io), J1 I/O186 (io), J2 I/O185 (io), J3 I/O184 (io), J4 I/O183 (io), J17 I/O96 (io), K1 I/O189 (io), K2 I/O187 (io), K3 I/O188 (io), K17 I/O95 (io), K18 I/O94 (io), K19 I/O93 (io), K20 I/O92 (io), L1 I/O190 (io), L2 I/O191 (io), L18 I/O90 (io), L19 I/O89 (io), L20 I/O91 (io), M2 I/O0/TOE (io), M3 I/O1 (io), M4 I/O2 (io), M17 I/O85 (io), M18 I/O86 (io), M19 I/O87 (io), M20 I/O88 (io), N1 I/O3 (io), N2 I/O4 (io), N3 I/O5 (io), N18 I/O82 (io), N19 I/O83 (io), N20 I/O84 (io), P1 I/O6 (io), P2 I/O7 (io), P3 I/O9 (io), P4 I/O12 (io), P17 I/O77 (io), P18 I/O80 (io), P20 I/O81 (io), R1 I/O8 (io), R2 I/O10 (io), R18 I/O76 (io), R19 I/O78 (io), R20 I/O79 (io), T1 I/O11 (io), T2 I/O13 (io), T3 I/O14 (io), T18 I/O74 (io), T19 I/O75 (io), U5 I/O21 (io), U7 I/O28 (io), U9 I/O37 (io), U12 I/O48 (io), U14 I/O58 (io), U16 I/O64 (io), U18 I/O71 (io), U19 I/O70 (io), U20 I/O73 (io), V1 I/O15 (io), V2 I/O16 (io), V3 I/O17 (io), V4 I/O20 (io), V5 I/O24 (io), V6 I/O27 (io), V7 I/O31 (io), V8 I/O34 (io), V9 I/O38 (io), V10 I/O42 (io), V12 I/O47 (io), V13 I/O51 (io), V14 I/O55 (io), V15 I/O59 (io), V16 I/O62 (io), V17 I/O65 (io), V18 I/O68 (io), V19 I/O69 (io), V20 I/O72 (io), W3 I/O19 (io), W5 I/O25 (io), W6 I/O29 (io), W7 I/O32 (io), W8 I/O35 (io), W9 I/O39 (io), W10 I/O41 (io), W11 I/O45 (io), W12 I/O46 (io), W13 I/O50 (io), W14 I/O53 (io), W15 I/O56 (io), W16 I/O60 (io), W18 I/O66 (io), Y1 I/O18 (io), Y3 I/O22 (io), Y4 I/O23 (io), Y5 I/O26 (io), Y6 I/O30 (io), Y7 I/O33 (io), Y8 I/O36 (io), Y9 I/O40 (io), Y10 I/O43 (io), Y11 I/O44 (io), Y13 I/O49 (io), Y14 I/O52 (io), Y15 I/O54 (io), Y16 I/O57 (io), Y17 I/O61 (io), Y18 I/O63 (io), Y19 I/O67 (io)
part B pins: C10 CLK0 (in), D10 CLK1 (in), J18 RESET (in), J20 TDO (out), L3 TMS (in), L4 TCK (in), M1 TDI (in), U11 GOE1 (in), V11 GOE0 (in)
part C pins: A1 GND (power), A17 NC, B3 NC, B18 NC, B19 NC, B20 NC, C3 NC, C5 NC, C18 NC, C19 NC, D3 NC, D4 GND (power), D6 VCC (power), D8 GND (power), D11 VCC (power), D13 GND (power), D15 VCC (power), D17 GND (power), D19 NC, E2 NC, F4 VCC (power), F17 VCC (power), H4 GND (power), H17 GND (power), J9 GND (power), J10 GND (power), J11 GND (power), J12 GND (power), J19 VCCIO (power), K4 VCC (power), K9 GND (power), K10 GND (power), K11 GND (power), K12 GND (power), L9 GND (power), L10 GND (power), L11 GND (power), L12 GND (power), L17 VCC (power), M9 GND (power), M10 GND (power), M11 GND (power), M12 GND (power), N4 GND (power), N17 GND (power), P19 NC, R3 NC, R4 VCC (power), R17 VCC (power), T4 NC, T17 NC, T20 NC, U1 NC, U2 NC, U3 NC, U4 GND (power), U6 VCC (power), U8 GND (power), U10 VCC (power), U13 GND (power), U15 VCC (power), U17 GND (power), W1 NC, W2 NC, W4 NC, W17 NC, W19 NC, W20 NC, Y2 NC, Y12 NC, Y20 NC

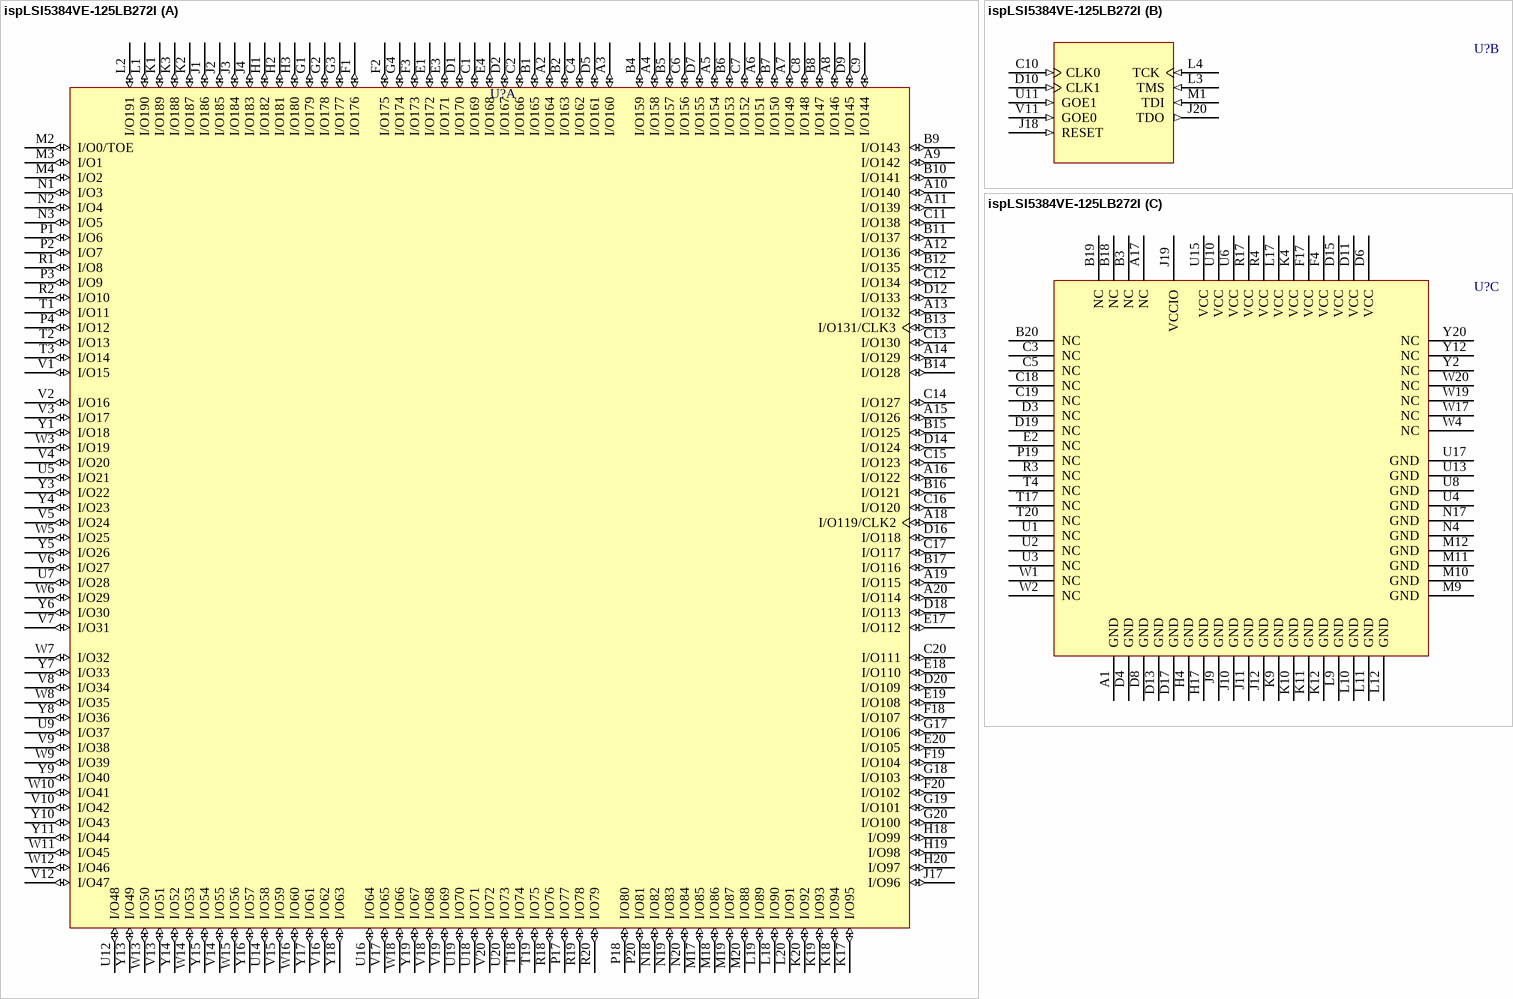
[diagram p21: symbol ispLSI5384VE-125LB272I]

## ispLSI5384VE-125LB272I
designator U?
ispLSI 5384VE SuperWIDE High Density PLD with 144 User I/Os, 7.5 ns, 3.3 V, Industrial Grade
footprint BGA272 (BGA, 272-Leads, Body 27x27mm, Pitch 1.27mm)
3D model 5384VE-BGA272 (272-Ball Ball Grid Array (BGA272))
part A pins: A2 I/O164 (io), A3 I/O160 (io), A4 I/O158 (io), A5 I/O154 (io), A6 I/O151 (io), A7 I/O149 (io), A8 I/O146 (io), A9 I/O142 (io), A10 I/O140 (io), A11 I/O139 (io), A12 I/O136 (io), A13 I/O132 (io), A14 I/O129 (io), A15 I/O126 (io), A16 I/O122 (io), A18 I/O119/CLK2 (io), A19 I/O115 (io), A20 I/O114 (io), B1 I/O165 (io), B2 I/O163 (io), B4 I/O159 (io), B5 I/O157 (io), B6 I/O153 (io), B7 I/O150 (io), B8 I/O147 (io), B9 I/O143 (io), B10 I/O141 (io), B11 I/O137 (io), B12 I/O135 (io), B13 I/O131/CLK3 (io), B14 I/O128 (io), B15 I/O125 (io), B16 I/O121 (io), B17 I/O116 (io), C1 I/O169 (io), C2 I/O166 (io), C4 I/O162 (io), C6 I/O156 (io), C7 I/O152 (io), C8 I/O148 (io), C9 I/O144 (io), C11 I/O138 (io), C12 I/O134 (io), C13 I/O130 (io), C14 I/O127 (io), C15 I/O123 (io), C16 I/O120 (io), C17 I/O117 (io), C20 I/O111 (io), D1 I/O170 (io), D2 I/O167 (io), D5 I/O161 (io), D7 I/O155 (io), D9 I/O145 (io), D12 I/O133 (io), D14 I/O124 (io), D16 I/O118 (io), D18 I/O113 (io), D20 I/O109 (io), E1 I/O172 (io), E3 I/O171 (io), E4 I/O168 (io), E17 I/O112 (io), E18 I/O110 (io), E19 I/O108 (io), E20 I/O105 (io), F1 I/O176 (io), F2 I/O175 (io), F3 I/O173 (io), F18 I/O107 (io), F19 I/O104 (io), F20 I/O102 (io), G1 I/O179 (io), G2 I/O178 (io), G3 I/O177 (io), G4 I/O174 (io), G17 I/O106 (io), G18 I/O103 (io), G19 I/O101 (io), G20 I/O100 (io), H1 I/O182 (io), H2 I/O181 (io), H3 I/O180 (io), H18 I/O99 (io), H19 I/O98 (io), H20 I/O97 (io), J1 I/O186 (io), J2 I/O185 (io), J3 I/O184 (io), J4 I/O183 (io), J17 I/O96 (io), K1 I/O189 (io), K2 I/O187 (io), K3 I/O188 (io), K17 I/O95 (io), K18 I/O94 (io), K19 I/O93 (io), K20 I/O92 (io), L1 I/O190 (io), L2 I/O191 (io), L18 I/O90 (io), L19 I/O89 (io), L20 I/O91 (io), M2 I/O0/TOE (io), M3 I/O1 (io), M4 I/O2 (io), M17 I/O85 (io), M18 I/O86 (io), M19 I/O87 (io), M20 I/O88 (io), N1 I/O3 (io), N2 I/O4 (io), N3 I/O5 (io), N18 I/O82 (io), N19 I/O83 (io), N20 I/O84 (io), P1 I/O6 (io), P2 I/O7 (io), P3 I/O9 (io), P4 I/O12 (io), P17 I/O77 (io), P18 I/O80 (io), P20 I/O81 (io), R1 I/O8 (io), R2 I/O10 (io), R18 I/O76 (io), R19 I/O78 (io), R20 I/O79 (io), T1 I/O11 (io), T2 I/O13 (io), T3 I/O14 (io), T18 I/O74 (io), T19 I/O75 (io), U5 I/O21 (io), U7 I/O28 (io), U9 I/O37 (io), U12 I/O48 (io), U14 I/O58 (io), U16 I/O64 (io), U18 I/O71 (io), U19 I/O70 (io), U20 I/O73 (io), V1 I/O15 (io), V2 I/O16 (io), V3 I/O17 (io), V4 I/O20 (io), V5 I/O24 (io), V6 I/O27 (io), V7 I/O31 (io), V8 I/O34 (io), V9 I/O38 (io), V10 I/O42 (io), V12 I/O47 (io), V13 I/O51 (io), V14 I/O55 (io), V15 I/O59 (io), V16 I/O62 (io), V17 I/O65 (io), V18 I/O68 (io), V19 I/O69 (io), V20 I/O72 (io), W3 I/O19 (io), W5 I/O25 (io), W6 I/O29 (io), W7 I/O32 (io), W8 I/O35 (io), W9 I/O39 (io), W10 I/O41 (io), W11 I/O45 (io), W12 I/O46 (io), W13 I/O50 (io), W14 I/O53 (io), W15 I/O56 (io), W16 I/O60 (io), W18 I/O66 (io), Y1 I/O18 (io), Y3 I/O22 (io), Y4 I/O23 (io), Y5 I/O26 (io), Y6 I/O30 (io), Y7 I/O33 (io), Y8 I/O36 (io), Y9 I/O40 (io), Y10 I/O43 (io), Y11 I/O44 (io), Y13 I/O49 (io), Y14 I/O52 (io), Y15 I/O54 (io), Y16 I/O57 (io), Y17 I/O61 (io), Y18 I/O63 (io), Y19 I/O67 (io)
part B pins: C10 CLK0 (in), D10 CLK1 (in), J18 RESET (in), J20 TDO (out), L3 TMS (in), L4 TCK (in), M1 TDI (in), U11 GOE1 (in), V11 GOE0 (in)
part C pins: A1 GND (power), A17 NC, B3 NC, B18 NC, B19 NC, B20 NC, C3 NC, C5 NC, C18 NC, C19 NC, D3 NC, D4 GND (power), D6 VCC (power), D8 GND (power), D11 VCC (power), D13 GND (power), D15 VCC (power), D17 GND (power), D19 NC, E2 NC, F4 VCC (power), F17 VCC (power), H4 GND (power), H17 GND (power), J9 GND (power), J10 GND (power), J11 GND (power), J12 GND (power), J19 VCCIO (power), K4 VCC (power), K9 GND (power), K10 GND (power), K11 GND (power), K12 GND (power), L9 GND (power), L10 GND (power), L11 GND (power), L12 GND (power), L17 VCC (power), M9 GND (power), M10 GND (power), M11 GND (power), M12 GND (power), N4 GND (power), N17 GND (power), P19 NC, R3 NC, R4 VCC (power), R17 VCC (power), T4 NC, T17 NC, T20 NC, U1 NC, U2 NC, U3 NC, U4 GND (power), U6 VCC (power), U8 GND (power), U10 VCC (power), U13 GND (power), U15 VCC (power), U17 GND (power), W1 NC, W2 NC, W4 NC, W17 NC, W19 NC, W20 NC, Y2 NC, Y12 NC, Y20 NC

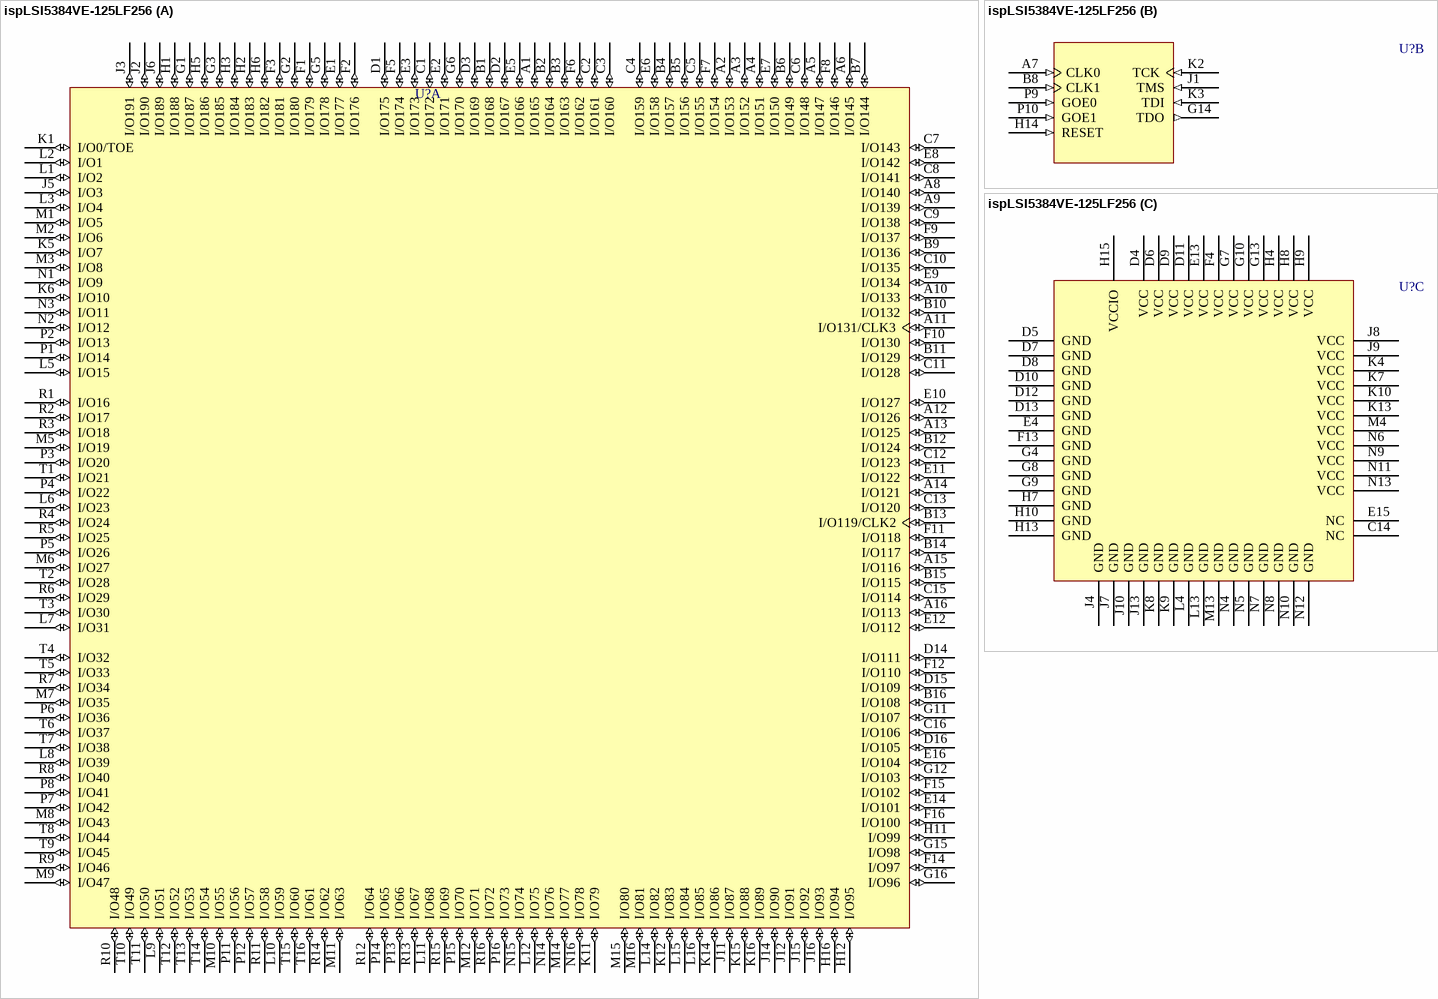
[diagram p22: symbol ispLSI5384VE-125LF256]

## ispLSI5384VE-125LF256
designator U?
ispLSI 5384VE SuperWIDE High Density PLD with 192 User I/Os, 7.5 ns, 3.3 V, Commercial Grade
footprint fpBGA256 (BGA, 256-Leads, Body 17x17mm, Pitch 1mm)
3D model 5384VE-fpBGA256 (256-Ball Fine Pitch Ball Grid Array (fpBGA256))
part A pins: A1 I/O165 (io), A2 I/O153 (io), A3 I/O152 (io), A4 I/O151 (io), A5 I/O147 (io), A6 I/O145 (io), A8 I/O140 (io), A9 I/O139 (io), A10 I/O133 (io), A11 I/O131/CLK3 (io), A12 I/O126 (io), A13 I/O125 (io), A14 I/O121 (io), A15 I/O116 (io), A16 I/O113 (io), B1 I/O168 (io), B2 I/O164 (io), B3 I/O163 (io), B4 I/O157 (io), B5 I/O156 (io), B6 I/O149 (io), B7 I/O144 (io), B9 I/O136 (io), B10 I/O132 (io), B11 I/O129 (io), B12 I/O124 (io), B13 I/O119/CLK2 (io), B14 I/O117 (io), B15 I/O115 (io), B16 I/O108 (io), C1 I/O172 (io), C2 I/O161 (io), C3 I/O160 (io), C4 I/O159 (io), C5 I/O155 (io), C6 I/O148 (io), C7 I/O143 (io), C8 I/O141 (io), C9 I/O138 (io), C10 I/O135 (io), C11 I/O128 (io), C12 I/O123 (io), C13 I/O120 (io), C15 I/O114 (io), C16 I/O106 (io), D1 I/O175 (io), D2 I/O167 (io), D3 I/O169 (io), D14 I/O111 (io), D15 I/O109 (io), D16 I/O105 (io), E1 I/O177 (io), E2 I/O171 (io), E3 I/O173 (io), E5 I/O166 (io), E6 I/O158 (io), E7 I/O150 (io), E8 I/O142 (io), E9 I/O134 (io), E10 I/O127 (io), E11 I/O122 (io), E12 I/O112 (io), E14 I/O101 (io), E16 I/O104 (io), F1 I/O179 (io), F2 I/O176 (io), F3 I/O181 (io), F5 I/O174 (io), F6 I/O162 (io), F7 I/O154 (io), F8 I/O146 (io), F9 I/O137 (io), F10 I/O130 (io), F11 I/O118 (io), F12 I/O110 (io), F14 I/O97 (io), F15 I/O102 (io), F16 I/O100 (io), G1 I/O187 (io), G2 I/O180 (io), G3 I/O185 (io), G5 I/O178 (io), G6 I/O170 (io), G11 I/O107 (io), G12 I/O103 (io), G15 I/O98 (io), G16 I/O96 (io), H1 I/O188 (io), H2 I/O183 (io), H3 I/O184 (io), H5 I/O186 (io), H6 I/O182 (io), H11 I/O99 (io), H12 I/O95 (io), H16 I/O94 (io), J2 I/O190 (io), J3 I/O191 (io), J5 I/O3 (io), J6 I/O189 (io), J11 I/O87 (io), J12 I/O91 (io), J14 I/O90 (io), J15 I/O92 (io), J16 I/O93 (io), K1 I/O0/TOE (io), K5 I/O7 (io), K6 I/O10 (io), K11 I/O79 (io), K12 I/O83 (io), K14 I/O86 (io), K15 I/O88 (io), K16 I/O89 (io), L1 I/O2 (io), L2 I/O1 (io), L3 I/O4 (io), L5 I/O15 (io), L6 I/O23 (io), L7 I/O31 (io), L8 I/O39 (io), L9 I/O51 (io), L10 I/O59 (io), L11 I/O68 (io), L12 I/O75 (io), L14 I/O82 (io), L15 I/O84 (io), L16 I/O85 (io), M1 I/O5 (io), M2 I/O6 (io), M3 I/O8 (io), M5 I/O19 (io), M6 I/O27 (io), M7 I/O35 (io), M8 I/O43 (io), M9 I/O47 (io), M10 I/O55 (io), M11 I/O63 (io), M12 I/O71 (io), M14 I/O77 (io), M15 I/O80 (io), M16 I/O81 (io), N1 I/O9 (io), N2 I/O12 (io), N3 I/O11 (io), N14 I/O76 (io), N15 I/O74 (io), N16 I/O78 (io), P1 I/O14 (io), P2 I/O13 (io), P3 I/O20 (io), P4 I/O22 (io), P5 I/O26 (io), P6 I/O36 (io), P7 I/O42 (io), P8 I/O41 (io), P11 I/O56 (io), P12 I/O57 (io), P13 I/O66 (io), P14 I/O65 (io), P15 I/O70 (io), P16 I/O73 (io), R1 I/O16 (io), R2 I/O17 (io), R3 I/O18 (io), R4 I/O24 (io), R5 I/O25 (io), R6 I/O29 (io), R7 I/O34 (io), R8 I/O40 (io), R9 I/O46 (io), R10 I/O48 (io), R11 I/O58 (io), R12 I/O64 (io), R13 I/O67 (io), R14 I/O62 (io), R15 I/O69 (io), R16 I/O72 (io), T1 I/O21 (io), T2 I/O28 (io), T3 I/O30 (io), T4 I/O32 (io), T5 I/O33 (io), T6 I/O37 (io), T7 I/O38 (io), T8 I/O44 (io), T9 I/O45 (io), T10 I/O49 (io), T11 I/O50 (io), T12 I/O52 (io), T13 I/O53 (io), T14 I/O54 (io), T15 I/O60 (io), T16 I/O61 (io)
part B pins: A7 CLK0 (in), B8 CLK1 (in), G14 TDO (out), H14 RESET (in), J1 TMS (in), K2 TCK (in), K3 TDI (in), P9 GOE0 (in), P10 GOE1 (in)
part C pins: C14 NC, D4 VCC (power), D5 GND (power), D6 VCC (power), D7 GND (power), D8 GND (power), D9 VCC (power), D10 GND (power), D11 VCC (power), D12 GND (power), D13 GND (power), E4 GND (power), E13 VCC (power), E15 NC, F4 VCC (power), F13 GND (power), G4 GND (power), G7 VCC (power), G8 GND (power), G9 GND (power), G10 VCC (power), G13 VCC (power), H4 VCC (power), H7 GND (power), H8 VCC (power), H9 VCC (power), H10 GND (power), H13 GND (power), H15 VCCIO (power), J4 GND (power), J7 GND (power), J8 VCC (power), J9 VCC (power), J10 GND (power), J13 GND (power), K4 VCC (power), K7 VCC (power), K8 GND (power), K9 GND (power), K10 VCC (power), K13 VCC (power), L4 GND (power), L13 GND (power), M4 VCC (power), M13 GND (power), N4 GND (power), N5 GND (power), N6 VCC (power), N7 GND (power), N8 GND (power), N9 VCC (power), N10 GND (power), N11 VCC (power), N12 GND (power), N13 VCC (power)

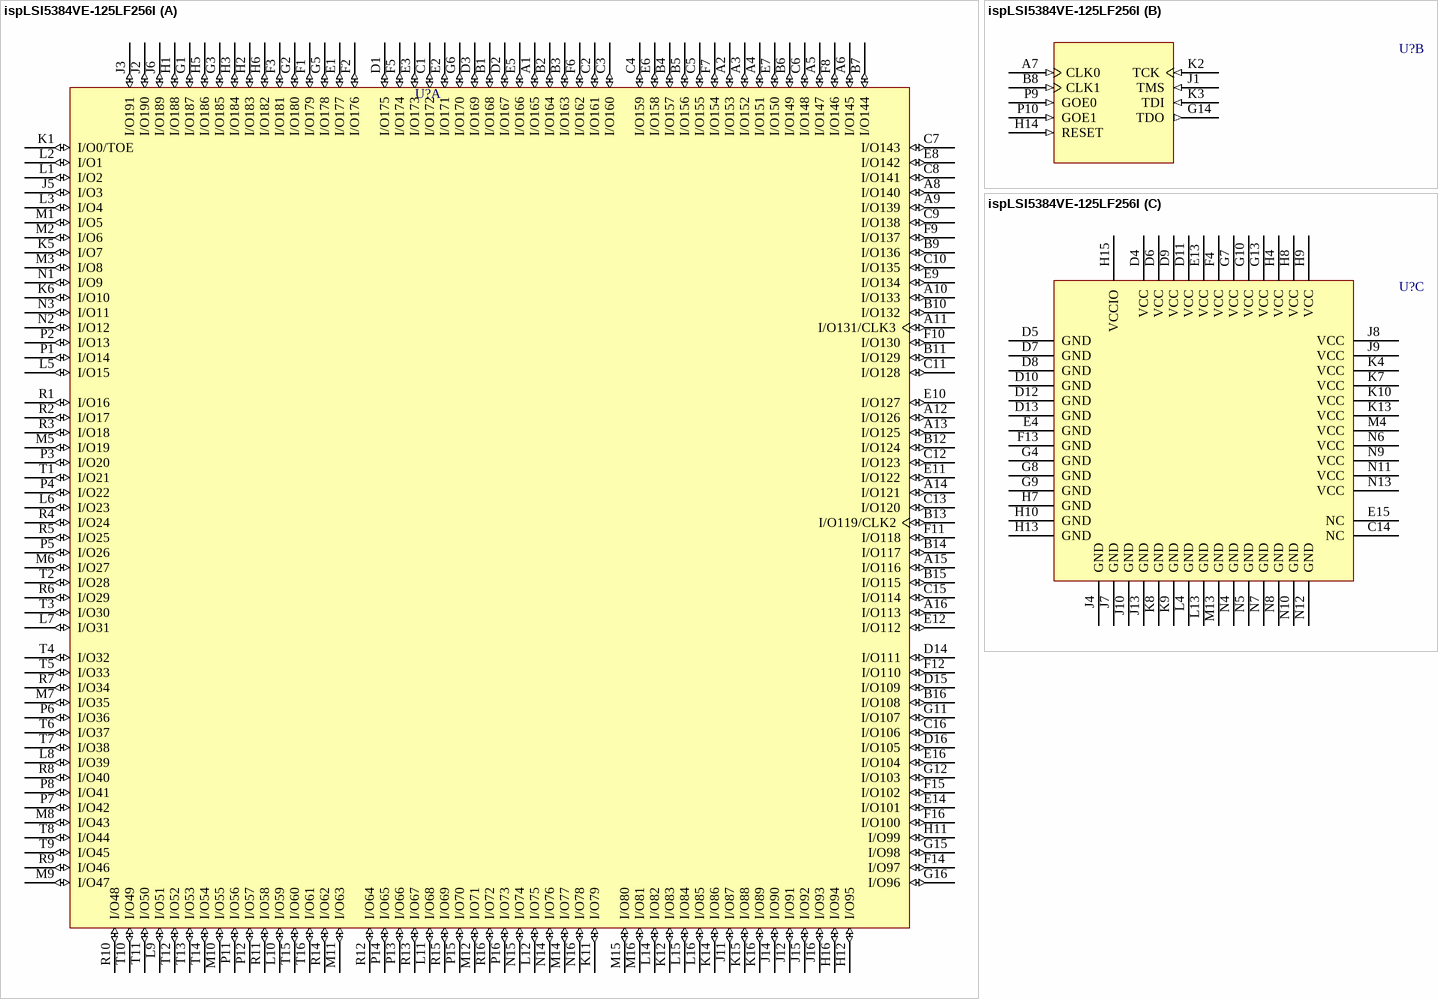
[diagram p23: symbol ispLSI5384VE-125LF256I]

## ispLSI5384VE-125LF256I
designator U?
ispLSI 5384VE SuperWIDE High Density PLD with 192 User I/Os, 7.5 ns, 3.3 V, Industrial Grade
footprint fpBGA256 (BGA, 256-Leads, Body 17x17mm, Pitch 1mm)
3D model 5384VE-fpBGA256 (256-Ball Fine Pitch Ball Grid Array (fpBGA256))
part A pins: A1 I/O165 (io), A2 I/O153 (io), A3 I/O152 (io), A4 I/O151 (io), A5 I/O147 (io), A6 I/O145 (io), A8 I/O140 (io), A9 I/O139 (io), A10 I/O133 (io), A11 I/O131/CLK3 (io), A12 I/O126 (io), A13 I/O125 (io), A14 I/O121 (io), A15 I/O116 (io), A16 I/O113 (io), B1 I/O168 (io), B2 I/O164 (io), B3 I/O163 (io), B4 I/O157 (io), B5 I/O156 (io), B6 I/O149 (io), B7 I/O144 (io), B9 I/O136 (io), B10 I/O132 (io), B11 I/O129 (io), B12 I/O124 (io), B13 I/O119/CLK2 (io), B14 I/O117 (io), B15 I/O115 (io), B16 I/O108 (io), C1 I/O172 (io), C2 I/O161 (io), C3 I/O160 (io), C4 I/O159 (io), C5 I/O155 (io), C6 I/O148 (io), C7 I/O143 (io), C8 I/O141 (io), C9 I/O138 (io), C10 I/O135 (io), C11 I/O128 (io), C12 I/O123 (io), C13 I/O120 (io), C15 I/O114 (io), C16 I/O106 (io), D1 I/O175 (io), D2 I/O167 (io), D3 I/O169 (io), D14 I/O111 (io), D15 I/O109 (io), D16 I/O105 (io), E1 I/O177 (io), E2 I/O171 (io), E3 I/O173 (io), E5 I/O166 (io), E6 I/O158 (io), E7 I/O150 (io), E8 I/O142 (io), E9 I/O134 (io), E10 I/O127 (io), E11 I/O122 (io), E12 I/O112 (io), E14 I/O101 (io), E16 I/O104 (io), F1 I/O179 (io), F2 I/O176 (io), F3 I/O181 (io), F5 I/O174 (io), F6 I/O162 (io), F7 I/O154 (io), F8 I/O146 (io), F9 I/O137 (io), F10 I/O130 (io), F11 I/O118 (io), F12 I/O110 (io), F14 I/O97 (io), F15 I/O102 (io), F16 I/O100 (io), G1 I/O187 (io), G2 I/O180 (io), G3 I/O185 (io), G5 I/O178 (io), G6 I/O170 (io), G11 I/O107 (io), G12 I/O103 (io), G15 I/O98 (io), G16 I/O96 (io), H1 I/O188 (io), H2 I/O183 (io), H3 I/O184 (io), H5 I/O186 (io), H6 I/O182 (io), H11 I/O99 (io), H12 I/O95 (io), H16 I/O94 (io), J2 I/O190 (io), J3 I/O191 (io), J5 I/O3 (io), J6 I/O189 (io), J11 I/O87 (io), J12 I/O91 (io), J14 I/O90 (io), J15 I/O92 (io), J16 I/O93 (io), K1 I/O0/TOE (io), K5 I/O7 (io), K6 I/O10 (io), K11 I/O79 (io), K12 I/O83 (io), K14 I/O86 (io), K15 I/O88 (io), K16 I/O89 (io), L1 I/O2 (io), L2 I/O1 (io), L3 I/O4 (io), L5 I/O15 (io), L6 I/O23 (io), L7 I/O31 (io), L8 I/O39 (io), L9 I/O51 (io), L10 I/O59 (io), L11 I/O68 (io), L12 I/O75 (io), L14 I/O82 (io), L15 I/O84 (io), L16 I/O85 (io), M1 I/O5 (io), M2 I/O6 (io), M3 I/O8 (io), M5 I/O19 (io), M6 I/O27 (io), M7 I/O35 (io), M8 I/O43 (io), M9 I/O47 (io), M10 I/O55 (io), M11 I/O63 (io), M12 I/O71 (io), M14 I/O77 (io), M15 I/O80 (io), M16 I/O81 (io), N1 I/O9 (io), N2 I/O12 (io), N3 I/O11 (io), N14 I/O76 (io), N15 I/O74 (io), N16 I/O78 (io), P1 I/O14 (io), P2 I/O13 (io), P3 I/O20 (io), P4 I/O22 (io), P5 I/O26 (io), P6 I/O36 (io), P7 I/O42 (io), P8 I/O41 (io), P11 I/O56 (io), P12 I/O57 (io), P13 I/O66 (io), P14 I/O65 (io), P15 I/O70 (io), P16 I/O73 (io), R1 I/O16 (io), R2 I/O17 (io), R3 I/O18 (io), R4 I/O24 (io), R5 I/O25 (io), R6 I/O29 (io), R7 I/O34 (io), R8 I/O40 (io), R9 I/O46 (io), R10 I/O48 (io), R11 I/O58 (io), R12 I/O64 (io), R13 I/O67 (io), R14 I/O62 (io), R15 I/O69 (io), R16 I/O72 (io), T1 I/O21 (io), T2 I/O28 (io), T3 I/O30 (io), T4 I/O32 (io), T5 I/O33 (io), T6 I/O37 (io), T7 I/O38 (io), T8 I/O44 (io), T9 I/O45 (io), T10 I/O49 (io), T11 I/O50 (io), T12 I/O52 (io), T13 I/O53 (io), T14 I/O54 (io), T15 I/O60 (io), T16 I/O61 (io)
part B pins: A7 CLK0 (in), B8 CLK1 (in), G14 TDO (out), H14 RESET (in), J1 TMS (in), K2 TCK (in), K3 TDI (in), P9 GOE0 (in), P10 GOE1 (in)
part C pins: C14 NC, D4 VCC (power), D5 GND (power), D6 VCC (power), D7 GND (power), D8 GND (power), D9 VCC (power), D10 GND (power), D11 VCC (power), D12 GND (power), D13 GND (power), E4 GND (power), E13 VCC (power), E15 NC, F4 VCC (power), F13 GND (power), G4 GND (power), G7 VCC (power), G8 GND (power), G9 GND (power), G10 VCC (power), G13 VCC (power), H4 VCC (power), H7 GND (power), H8 VCC (power), H9 VCC (power), H10 GND (power), H13 GND (power), H15 VCCIO (power), J4 GND (power), J7 GND (power), J8 VCC (power), J9 VCC (power), J10 GND (power), J13 GND (power), K4 VCC (power), K7 VCC (power), K8 GND (power), K9 GND (power), K10 VCC (power), K13 VCC (power), L4 GND (power), L13 GND (power), M4 VCC (power), M13 GND (power), N4 GND (power), N5 GND (power), N6 VCC (power), N7 GND (power), N8 GND (power), N9 VCC (power), N10 GND (power), N11 VCC (power), N12 GND (power), N13 VCC (power)

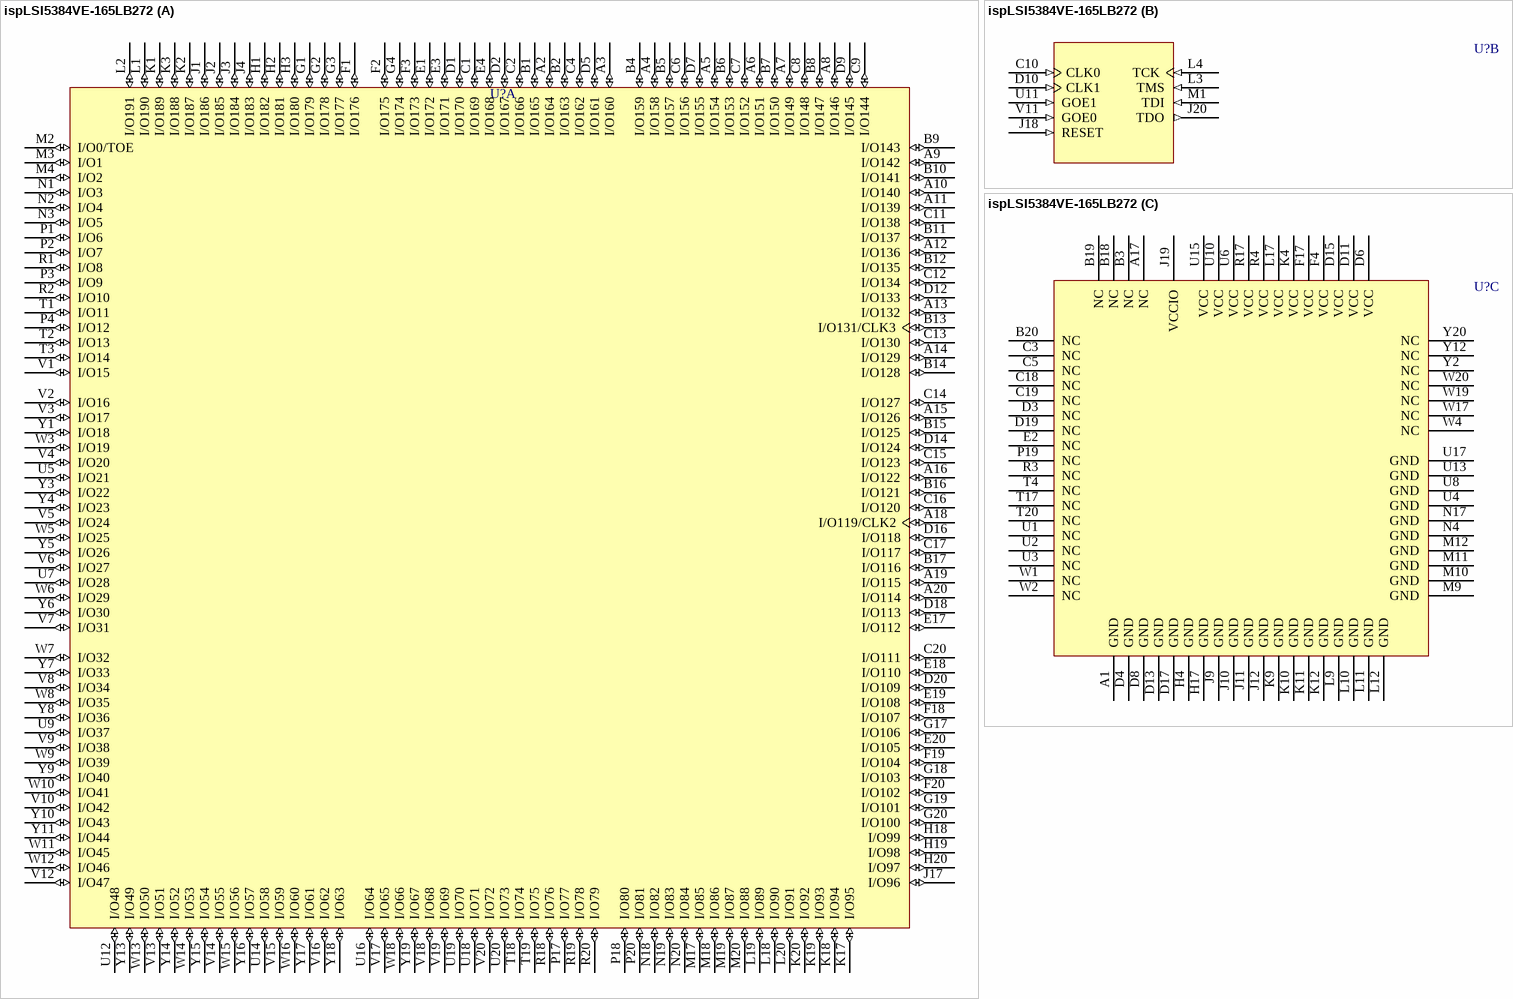
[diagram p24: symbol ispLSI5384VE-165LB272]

## ispLSI5384VE-165LB272
designator U?
ispLSI 5384VE SuperWIDE High Density PLD with 144 User I/Os, 6.0 ns, 3.3 V, Commercial Grade
footprint BGA272 (BGA, 272-Leads, Body 27x27mm, Pitch 1.27mm)
3D model 5384VE-BGA272 (272-Ball Ball Grid Array (BGA272))
part A pins: A2 I/O164 (io), A3 I/O160 (io), A4 I/O158 (io), A5 I/O154 (io), A6 I/O151 (io), A7 I/O149 (io), A8 I/O146 (io), A9 I/O142 (io), A10 I/O140 (io), A11 I/O139 (io), A12 I/O136 (io), A13 I/O132 (io), A14 I/O129 (io), A15 I/O126 (io), A16 I/O122 (io), A18 I/O119/CLK2 (io), A19 I/O115 (io), A20 I/O114 (io), B1 I/O165 (io), B2 I/O163 (io), B4 I/O159 (io), B5 I/O157 (io), B6 I/O153 (io), B7 I/O150 (io), B8 I/O147 (io), B9 I/O143 (io), B10 I/O141 (io), B11 I/O137 (io), B12 I/O135 (io), B13 I/O131/CLK3 (io), B14 I/O128 (io), B15 I/O125 (io), B16 I/O121 (io), B17 I/O116 (io), C1 I/O169 (io), C2 I/O166 (io), C4 I/O162 (io), C6 I/O156 (io), C7 I/O152 (io), C8 I/O148 (io), C9 I/O144 (io), C11 I/O138 (io), C12 I/O134 (io), C13 I/O130 (io), C14 I/O127 (io), C15 I/O123 (io), C16 I/O120 (io), C17 I/O117 (io), C20 I/O111 (io), D1 I/O170 (io), D2 I/O167 (io), D5 I/O161 (io), D7 I/O155 (io), D9 I/O145 (io), D12 I/O133 (io), D14 I/O124 (io), D16 I/O118 (io), D18 I/O113 (io), D20 I/O109 (io), E1 I/O172 (io), E3 I/O171 (io), E4 I/O168 (io), E17 I/O112 (io), E18 I/O110 (io), E19 I/O108 (io), E20 I/O105 (io), F1 I/O176 (io), F2 I/O175 (io), F3 I/O173 (io), F18 I/O107 (io), F19 I/O104 (io), F20 I/O102 (io), G1 I/O179 (io), G2 I/O178 (io), G3 I/O177 (io), G4 I/O174 (io), G17 I/O106 (io), G18 I/O103 (io), G19 I/O101 (io), G20 I/O100 (io), H1 I/O182 (io), H2 I/O181 (io), H3 I/O180 (io), H18 I/O99 (io), H19 I/O98 (io), H20 I/O97 (io), J1 I/O186 (io), J2 I/O185 (io), J3 I/O184 (io), J4 I/O183 (io), J17 I/O96 (io), K1 I/O189 (io), K2 I/O187 (io), K3 I/O188 (io), K17 I/O95 (io), K18 I/O94 (io), K19 I/O93 (io), K20 I/O92 (io), L1 I/O190 (io), L2 I/O191 (io), L18 I/O90 (io), L19 I/O89 (io), L20 I/O91 (io), M2 I/O0/TOE (io), M3 I/O1 (io), M4 I/O2 (io), M17 I/O85 (io), M18 I/O86 (io), M19 I/O87 (io), M20 I/O88 (io), N1 I/O3 (io), N2 I/O4 (io), N3 I/O5 (io), N18 I/O82 (io), N19 I/O83 (io), N20 I/O84 (io), P1 I/O6 (io), P2 I/O7 (io), P3 I/O9 (io), P4 I/O12 (io), P17 I/O77 (io), P18 I/O80 (io), P20 I/O81 (io), R1 I/O8 (io), R2 I/O10 (io), R18 I/O76 (io), R19 I/O78 (io), R20 I/O79 (io), T1 I/O11 (io), T2 I/O13 (io), T3 I/O14 (io), T18 I/O74 (io), T19 I/O75 (io), U5 I/O21 (io), U7 I/O28 (io), U9 I/O37 (io), U12 I/O48 (io), U14 I/O58 (io), U16 I/O64 (io), U18 I/O71 (io), U19 I/O70 (io), U20 I/O73 (io), V1 I/O15 (io), V2 I/O16 (io), V3 I/O17 (io), V4 I/O20 (io), V5 I/O24 (io), V6 I/O27 (io), V7 I/O31 (io), V8 I/O34 (io), V9 I/O38 (io), V10 I/O42 (io), V12 I/O47 (io), V13 I/O51 (io), V14 I/O55 (io), V15 I/O59 (io), V16 I/O62 (io), V17 I/O65 (io), V18 I/O68 (io), V19 I/O69 (io), V20 I/O72 (io), W3 I/O19 (io), W5 I/O25 (io), W6 I/O29 (io), W7 I/O32 (io), W8 I/O35 (io), W9 I/O39 (io), W10 I/O41 (io), W11 I/O45 (io), W12 I/O46 (io), W13 I/O50 (io), W14 I/O53 (io), W15 I/O56 (io), W16 I/O60 (io), W18 I/O66 (io), Y1 I/O18 (io), Y3 I/O22 (io), Y4 I/O23 (io), Y5 I/O26 (io), Y6 I/O30 (io), Y7 I/O33 (io), Y8 I/O36 (io), Y9 I/O40 (io), Y10 I/O43 (io), Y11 I/O44 (io), Y13 I/O49 (io), Y14 I/O52 (io), Y15 I/O54 (io), Y16 I/O57 (io), Y17 I/O61 (io), Y18 I/O63 (io), Y19 I/O67 (io)
part B pins: C10 CLK0 (in), D10 CLK1 (in), J18 RESET (in), J20 TDO (out), L3 TMS (in), L4 TCK (in), M1 TDI (in), U11 GOE1 (in), V11 GOE0 (in)
part C pins: A1 GND (power), A17 NC, B3 NC, B18 NC, B19 NC, B20 NC, C3 NC, C5 NC, C18 NC, C19 NC, D3 NC, D4 GND (power), D6 VCC (power), D8 GND (power), D11 VCC (power), D13 GND (power), D15 VCC (power), D17 GND (power), D19 NC, E2 NC, F4 VCC (power), F17 VCC (power), H4 GND (power), H17 GND (power), J9 GND (power), J10 GND (power), J11 GND (power), J12 GND (power), J19 VCCIO (power), K4 VCC (power), K9 GND (power), K10 GND (power), K11 GND (power), K12 GND (power), L9 GND (power), L10 GND (power), L11 GND (power), L12 GND (power), L17 VCC (power), M9 GND (power), M10 GND (power), M11 GND (power), M12 GND (power), N4 GND (power), N17 GND (power), P19 NC, R3 NC, R4 VCC (power), R17 VCC (power), T4 NC, T17 NC, T20 NC, U1 NC, U2 NC, U3 NC, U4 GND (power), U6 VCC (power), U8 GND (power), U10 VCC (power), U13 GND (power), U15 VCC (power), U17 GND (power), W1 NC, W2 NC, W4 NC, W17 NC, W19 NC, W20 NC, Y2 NC, Y12 NC, Y20 NC

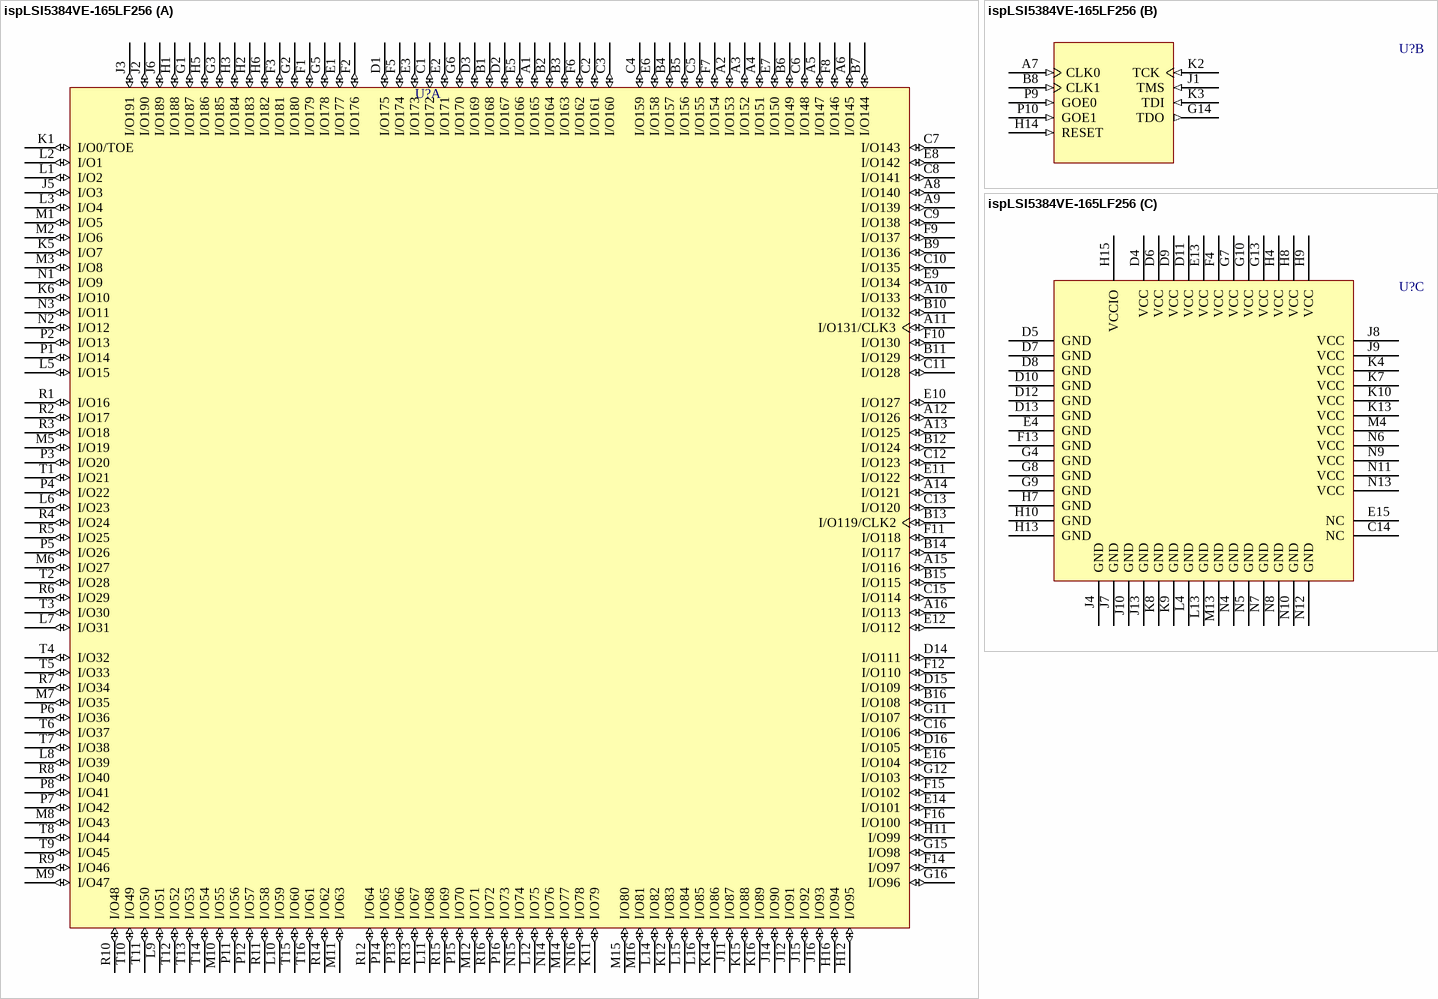
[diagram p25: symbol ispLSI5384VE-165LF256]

## ispLSI5384VE-165LF256
designator U?
ispLSI 5384VE SuperWIDE High Density PLD with 192 User I/Os, 6.0 ns, 3.3 V, Commercial Grade
footprint fpBGA256 (BGA, 256-Leads, Body 17x17mm, Pitch 1mm)
3D model 5384VE-fpBGA256 (256-Ball Fine Pitch Ball Grid Array (fpBGA256))
part A pins: A1 I/O165 (io), A2 I/O153 (io), A3 I/O152 (io), A4 I/O151 (io), A5 I/O147 (io), A6 I/O145 (io), A8 I/O140 (io), A9 I/O139 (io), A10 I/O133 (io), A11 I/O131/CLK3 (io), A12 I/O126 (io), A13 I/O125 (io), A14 I/O121 (io), A15 I/O116 (io), A16 I/O113 (io), B1 I/O168 (io), B2 I/O164 (io), B3 I/O163 (io), B4 I/O157 (io), B5 I/O156 (io), B6 I/O149 (io), B7 I/O144 (io), B9 I/O136 (io), B10 I/O132 (io), B11 I/O129 (io), B12 I/O124 (io), B13 I/O119/CLK2 (io), B14 I/O117 (io), B15 I/O115 (io), B16 I/O108 (io), C1 I/O172 (io), C2 I/O161 (io), C3 I/O160 (io), C4 I/O159 (io), C5 I/O155 (io), C6 I/O148 (io), C7 I/O143 (io), C8 I/O141 (io), C9 I/O138 (io), C10 I/O135 (io), C11 I/O128 (io), C12 I/O123 (io), C13 I/O120 (io), C15 I/O114 (io), C16 I/O106 (io), D1 I/O175 (io), D2 I/O167 (io), D3 I/O169 (io), D14 I/O111 (io), D15 I/O109 (io), D16 I/O105 (io), E1 I/O177 (io), E2 I/O171 (io), E3 I/O173 (io), E5 I/O166 (io), E6 I/O158 (io), E7 I/O150 (io), E8 I/O142 (io), E9 I/O134 (io), E10 I/O127 (io), E11 I/O122 (io), E12 I/O112 (io), E14 I/O101 (io), E16 I/O104 (io), F1 I/O179 (io), F2 I/O176 (io), F3 I/O181 (io), F5 I/O174 (io), F6 I/O162 (io), F7 I/O154 (io), F8 I/O146 (io), F9 I/O137 (io), F10 I/O130 (io), F11 I/O118 (io), F12 I/O110 (io), F14 I/O97 (io), F15 I/O102 (io), F16 I/O100 (io), G1 I/O187 (io), G2 I/O180 (io), G3 I/O185 (io), G5 I/O178 (io), G6 I/O170 (io), G11 I/O107 (io), G12 I/O103 (io), G15 I/O98 (io), G16 I/O96 (io), H1 I/O188 (io), H2 I/O183 (io), H3 I/O184 (io), H5 I/O186 (io), H6 I/O182 (io), H11 I/O99 (io), H12 I/O95 (io), H16 I/O94 (io), J2 I/O190 (io), J3 I/O191 (io), J5 I/O3 (io), J6 I/O189 (io), J11 I/O87 (io), J12 I/O91 (io), J14 I/O90 (io), J15 I/O92 (io), J16 I/O93 (io), K1 I/O0/TOE (io), K5 I/O7 (io), K6 I/O10 (io), K11 I/O79 (io), K12 I/O83 (io), K14 I/O86 (io), K15 I/O88 (io), K16 I/O89 (io), L1 I/O2 (io), L2 I/O1 (io), L3 I/O4 (io), L5 I/O15 (io), L6 I/O23 (io), L7 I/O31 (io), L8 I/O39 (io), L9 I/O51 (io), L10 I/O59 (io), L11 I/O68 (io), L12 I/O75 (io), L14 I/O82 (io), L15 I/O84 (io), L16 I/O85 (io), M1 I/O5 (io), M2 I/O6 (io), M3 I/O8 (io), M5 I/O19 (io), M6 I/O27 (io), M7 I/O35 (io), M8 I/O43 (io), M9 I/O47 (io), M10 I/O55 (io), M11 I/O63 (io), M12 I/O71 (io), M14 I/O77 (io), M15 I/O80 (io), M16 I/O81 (io), N1 I/O9 (io), N2 I/O12 (io), N3 I/O11 (io), N14 I/O76 (io), N15 I/O74 (io), N16 I/O78 (io), P1 I/O14 (io), P2 I/O13 (io), P3 I/O20 (io), P4 I/O22 (io), P5 I/O26 (io), P6 I/O36 (io), P7 I/O42 (io), P8 I/O41 (io), P11 I/O56 (io), P12 I/O57 (io), P13 I/O66 (io), P14 I/O65 (io), P15 I/O70 (io), P16 I/O73 (io), R1 I/O16 (io), R2 I/O17 (io), R3 I/O18 (io), R4 I/O24 (io), R5 I/O25 (io), R6 I/O29 (io), R7 I/O34 (io), R8 I/O40 (io), R9 I/O46 (io), R10 I/O48 (io), R11 I/O58 (io), R12 I/O64 (io), R13 I/O67 (io), R14 I/O62 (io), R15 I/O69 (io), R16 I/O72 (io), T1 I/O21 (io), T2 I/O28 (io), T3 I/O30 (io), T4 I/O32 (io), T5 I/O33 (io), T6 I/O37 (io), T7 I/O38 (io), T8 I/O44 (io), T9 I/O45 (io), T10 I/O49 (io), T11 I/O50 (io), T12 I/O52 (io), T13 I/O53 (io), T14 I/O54 (io), T15 I/O60 (io), T16 I/O61 (io)
part B pins: A7 CLK0 (in), B8 CLK1 (in), G14 TDO (out), H14 RESET (in), J1 TMS (in), K2 TCK (in), K3 TDI (in), P9 GOE0 (in), P10 GOE1 (in)
part C pins: C14 NC, D4 VCC (power), D5 GND (power), D6 VCC (power), D7 GND (power), D8 GND (power), D9 VCC (power), D10 GND (power), D11 VCC (power), D12 GND (power), D13 GND (power), E4 GND (power), E13 VCC (power), E15 NC, F4 VCC (power), F13 GND (power), G4 GND (power), G7 VCC (power), G8 GND (power), G9 GND (power), G10 VCC (power), G13 VCC (power), H4 VCC (power), H7 GND (power), H8 VCC (power), H9 VCC (power), H10 GND (power), H13 GND (power), H15 VCCIO (power), J4 GND (power), J7 GND (power), J8 VCC (power), J9 VCC (power), J10 GND (power), J13 GND (power), K4 VCC (power), K7 VCC (power), K8 GND (power), K9 GND (power), K10 VCC (power), K13 VCC (power), L4 GND (power), L13 GND (power), M4 VCC (power), M13 GND (power), N4 GND (power), N5 GND (power), N6 VCC (power), N7 GND (power), N8 GND (power), N9 VCC (power), N10 GND (power), N11 VCC (power), N12 GND (power), N13 VCC (power)

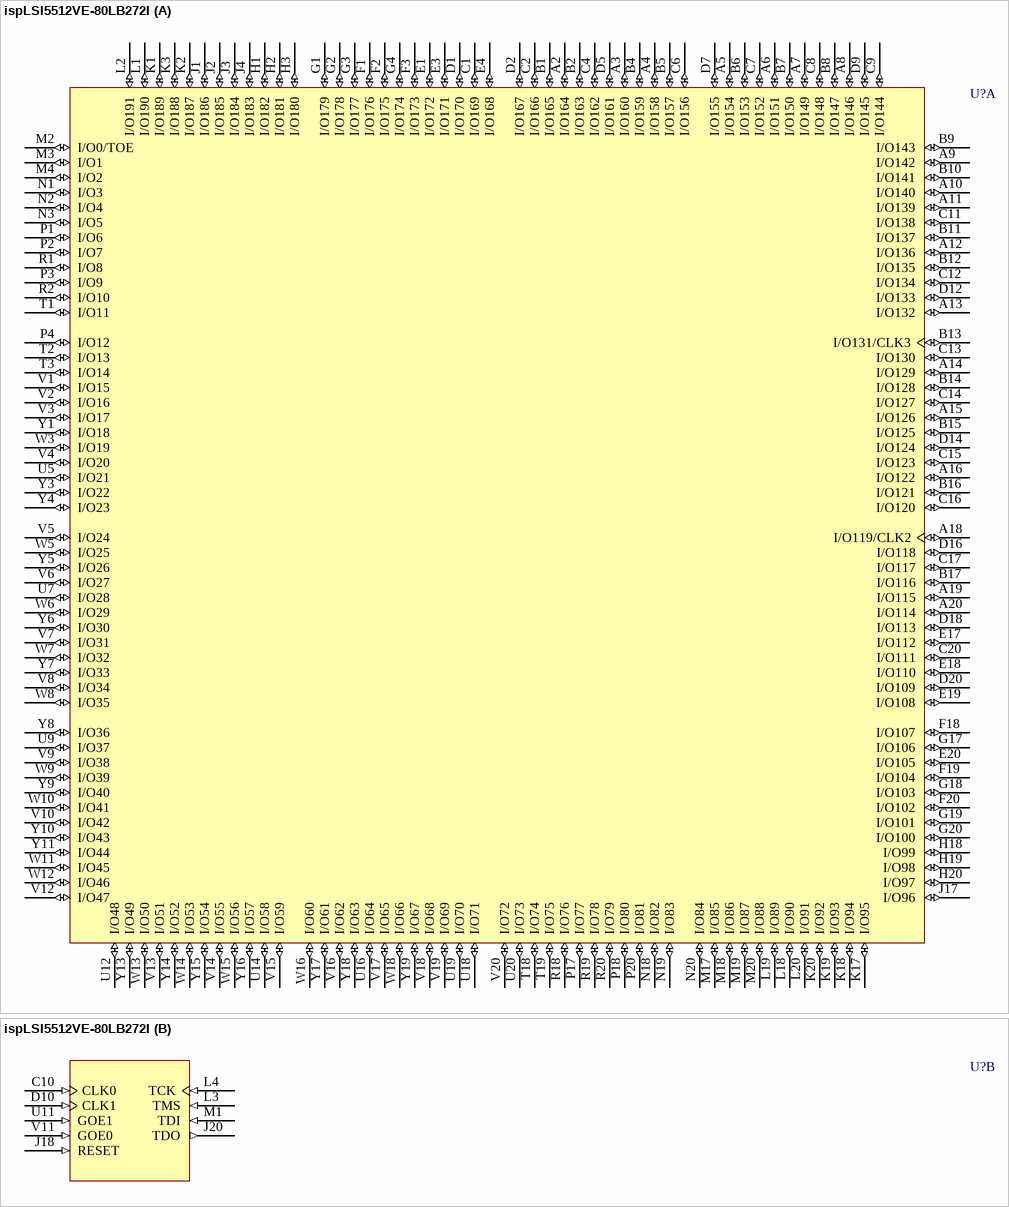
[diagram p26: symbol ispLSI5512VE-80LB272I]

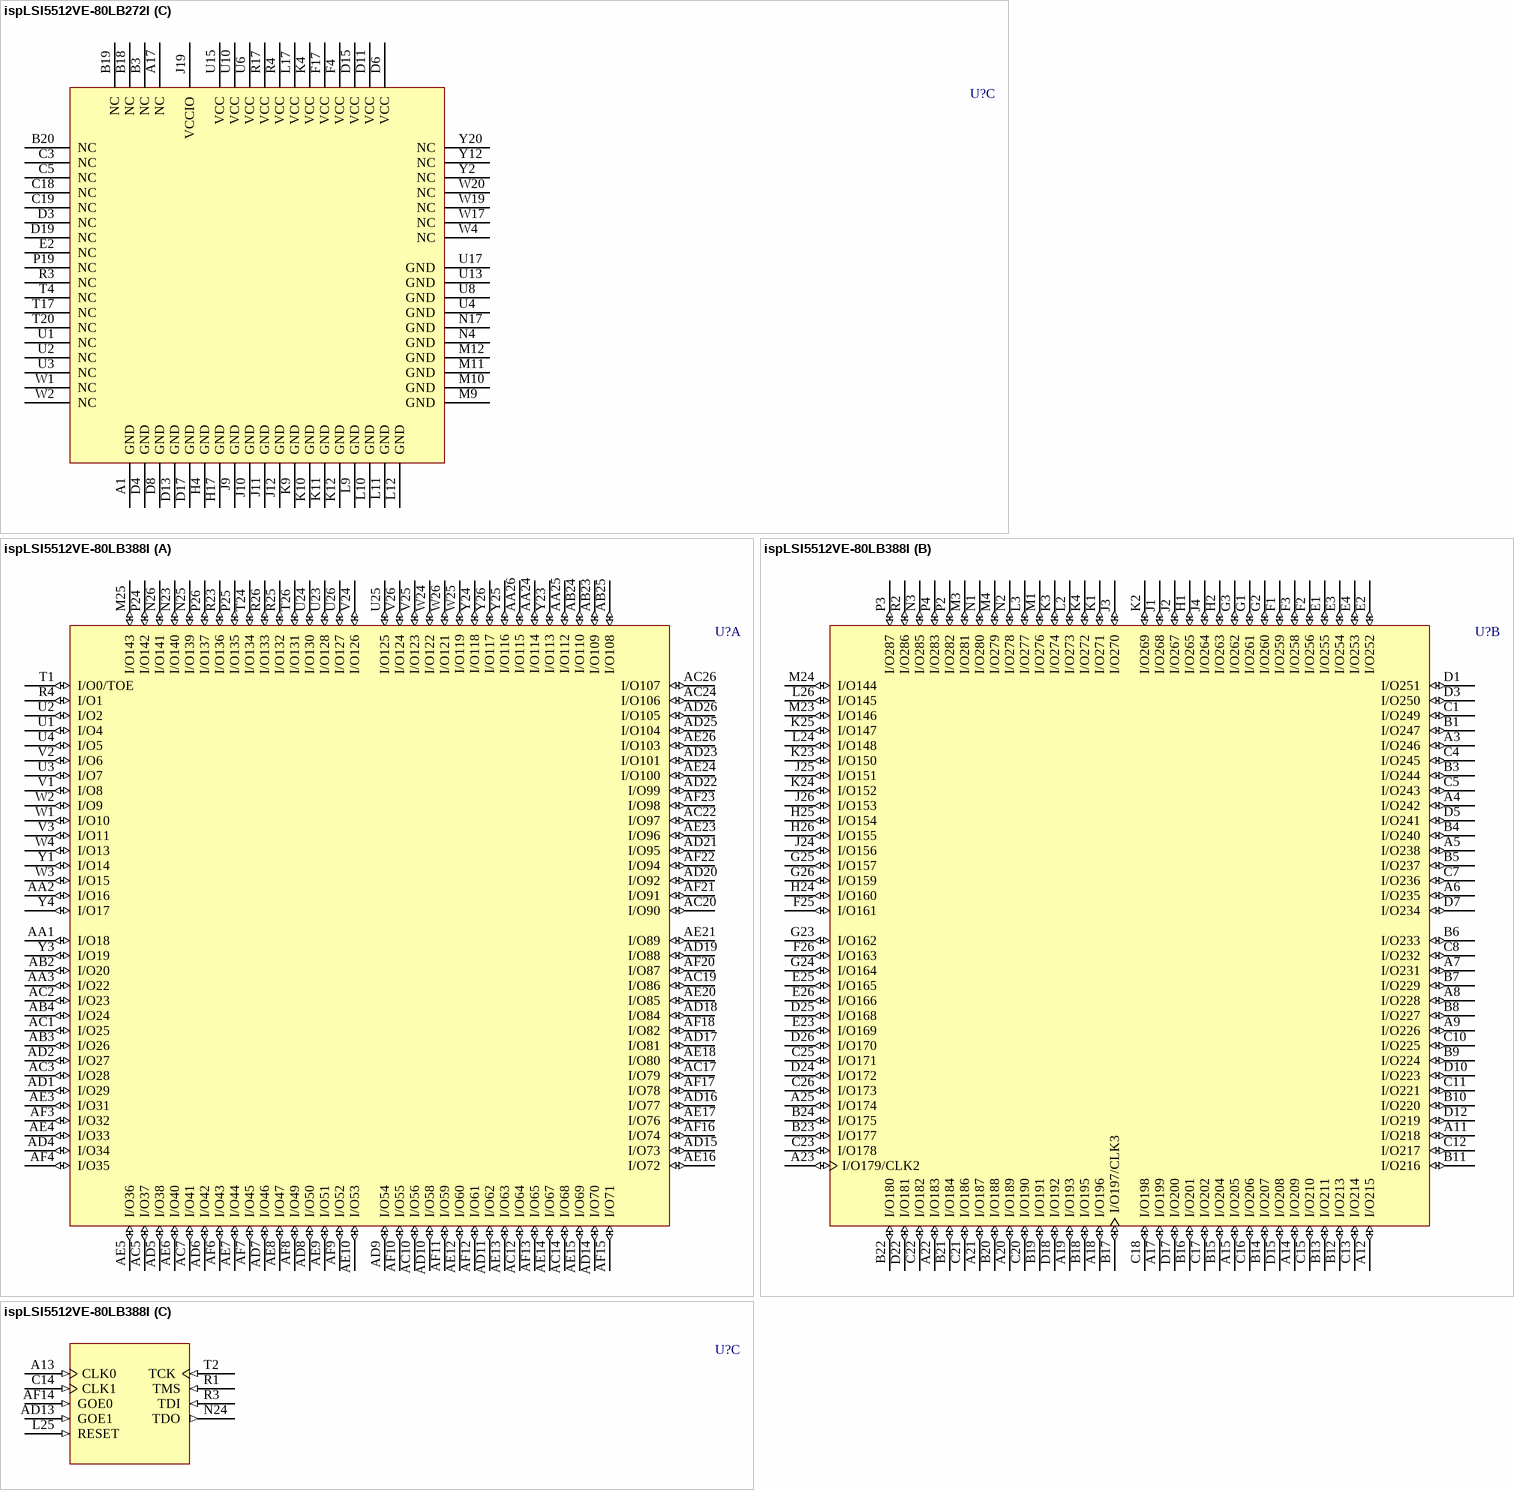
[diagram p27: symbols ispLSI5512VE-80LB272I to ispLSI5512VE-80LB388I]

## ispLSI5512VE-80LB272I
designator U?
ispLSI 5512VE SuperWIDE High Density PLD with 192 User I/Os, 12 ns, 3.3 V, Industrial Grade
footprint BGA272 (BGA, 272-Leads, Body 27x27mm, Pitch 1.27mm)
3D model 5512VE-BGA272 (272-Ball Ball Grid Array (BGA272))
part A pins: A2 I/O164 (io), A3 I/O160 (io), A4 I/O158 (io), A5 I/O154 (io), A6 I/O151 (io), A7 I/O149 (io), A8 I/O146 (io), A9 I/O142 (io), A10 I/O140 (io), A11 I/O139 (io), A12 I/O136 (io), A13 I/O132 (io), A14 I/O129 (io), A15 I/O126 (io), A16 I/O122 (io), A18 I/O119/CLK2 (io), A19 I/O115 (io), A20 I/O114 (io), B1 I/O165 (io), B2 I/O163 (io), B4 I/O159 (io), B5 I/O157 (io), B6 I/O153 (io), B7 I/O150 (io), B8 I/O147 (io), B9 I/O143 (io), B10 I/O141 (io), B11 I/O137 (io), B12 I/O135 (io), B13 I/O131/CLK3 (io), B14 I/O128 (io), B15 I/O125 (io), B16 I/O121 (io), B17 I/O116 (io), C1 I/O169 (io), C2 I/O166 (io), C4 I/O162 (io), C6 I/O156 (io), C7 I/O152 (io), C8 I/O148 (io), C9 I/O144 (io), C11 I/O138 (io), C12 I/O134 (io), C13 I/O130 (io), C14 I/O127 (io), C15 I/O123 (io), C16 I/O120 (io), C17 I/O117 (io), C20 I/O111 (io), D1 I/O170 (io), D2 I/O167 (io), D5 I/O161 (io), D7 I/O155 (io), D9 I/O145 (io), D12 I/O133 (io), D14 I/O124 (io), D16 I/O118 (io), D18 I/O113 (io), D20 I/O109 (io), E1 I/O172 (io), E3 I/O171 (io), E4 I/O168 (io), E17 I/O112 (io), E18 I/O110 (io), E19 I/O108 (io), E20 I/O105 (io), F1 I/O176 (io), F2 I/O175 (io), F3 I/O173 (io), F18 I/O107 (io), F19 I/O104 (io), F20 I/O102 (io), G1 I/O179 (io), G2 I/O178 (io), G3 I/O177 (io), G4 I/O174 (io), G17 I/O106 (io), G18 I/O103 (io), G19 I/O101 (io), G20 I/O100 (io), H1 I/O182 (io), H2 I/O181 (io), H3 I/O180 (io), H18 I/O99 (io), H19 I/O98 (io), H20 I/O97 (io), J1 I/O186 (io), J2 I/O185 (io), J3 I/O184 (io), J4 I/O183 (io), J17 I/O96 (io), K1 I/O189 (io), K2 I/O187 (io), K3 I/O188 (io), K17 I/O95 (io), K18 I/O94 (io), K19 I/O93 (io), K20 I/O92 (io), L1 I/O190 (io), L2 I/O191 (io), L18 I/O90 (io), L19 I/O89 (io), L20 I/O91 (io), M2 I/O0/TOE (io), M3 I/O1 (io), M4 I/O2 (io), M17 I/O85 (io), M18 I/O86 (io), M19 I/O87 (io), M20 I/O88 (io), N1 I/O3 (io), N2 I/O4 (io), N3 I/O5 (io), N18 I/O82 (io), N19 I/O83 (io), N20 I/O84 (io), P1 I/O6 (io), P2 I/O7 (io), P3 I/O9 (io), P4 I/O12 (io), P17 I/O77 (io), P18 I/O80 (io), P20 I/O81 (io), R1 I/O8 (io), R2 I/O10 (io), R18 I/O76 (io), R19 I/O78 (io), R20 I/O79 (io), T1 I/O11 (io), T2 I/O13 (io), T3 I/O14 (io), T18 I/O74 (io), T19 I/O75 (io), U5 I/O21 (io), U7 I/O28 (io), U9 I/O37 (io), U12 I/O48 (io), U14 I/O58 (io), U16 I/O64 (io), U18 I/O71 (io), U19 I/O70 (io), U20 I/O73 (io), V1 I/O15 (io), V2 I/O16 (io), V3 I/O17 (io), V4 I/O20 (io), V5 I/O24 (io), V6 I/O27 (io), V7 I/O31 (io), V8 I/O34 (io), V9 I/O38 (io), V10 I/O42 (io), V12 I/O47 (io), V13 I/O51 (io), V14 I/O55 (io), V15 I/O59 (io), V16 I/O62 (io), V17 I/O65 (io), V18 I/O68 (io), V19 I/O69 (io), V20 I/O72 (io), W3 I/O19 (io), W5 I/O25 (io), W6 I/O29 (io), W7 I/O32 (io), W8 I/O35 (io), W9 I/O39 (io), W10 I/O41 (io), W11 I/O45 (io), W12 I/O46 (io), W13 I/O50 (io), W14 I/O53 (io), W15 I/O56 (io), W16 I/O60 (io), W18 I/O66 (io), Y1 I/O18 (io), Y3 I/O22 (io), Y4 I/O23 (io), Y5 I/O26 (io), Y6 I/O30 (io), Y7 I/O33 (io), Y8 I/O36 (io), Y9 I/O40 (io), Y10 I/O43 (io), Y11 I/O44 (io), Y13 I/O49 (io), Y14 I/O52 (io), Y15 I/O54 (io), Y16 I/O57 (io), Y17 I/O61 (io), Y18 I/O63 (io), Y19 I/O67 (io)
part B pins: C10 CLK0 (in), D10 CLK1 (in), J18 RESET (in), J20 TDO (out), L3 TMS (in), L4 TCK (in), M1 TDI (in), U11 GOE1 (in), V11 GOE0 (in)
part C pins: A1 GND (power), A17 NC, B3 NC, B18 NC, B19 NC, B20 NC, C3 NC, C5 NC, C18 NC, C19 NC, D3 NC, D4 GND (power), D6 VCC (power), D8 GND (power), D11 VCC (power), D13 GND (power), D15 VCC (power), D17 GND (power), D19 NC, E2 NC, F4 VCC (power), F17 VCC (power), H4 GND (power), H17 GND (power), J9 GND (power), J10 GND (power), J11 GND (power), J12 GND (power), J19 VCCIO (power), K4 VCC (power), K9 GND (power), K10 GND (power), K11 GND (power), K12 GND (power), L9 GND (power), L10 GND (power), L11 GND (power), L12 GND (power), L17 VCC (power), M9 GND (power), M10 GND (power), M11 GND (power), M12 GND (power), N4 GND (power), N17 GND (power), P19 NC, R3 NC, R4 VCC (power), R17 VCC (power), T4 NC, T17 NC, T20 NC, U1 NC, U2 NC, U3 NC, U4 GND (power), U6 VCC (power), U8 GND (power), U10 VCC (power), U13 GND (power), U15 VCC (power), U17 GND (power), W1 NC, W2 NC, W4 NC, W17 NC, W19 NC, W20 NC, Y2 NC, Y12 NC, Y20 NC

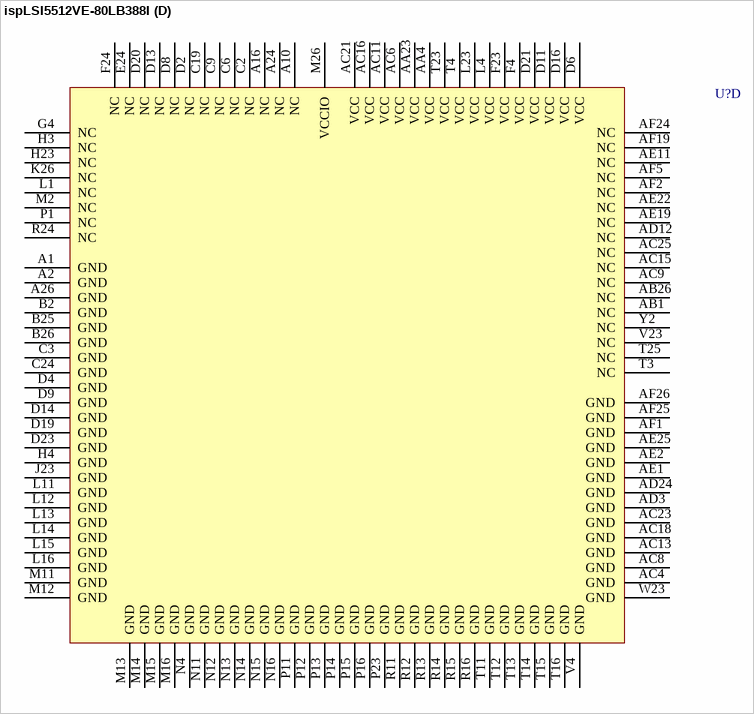
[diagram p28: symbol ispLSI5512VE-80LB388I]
